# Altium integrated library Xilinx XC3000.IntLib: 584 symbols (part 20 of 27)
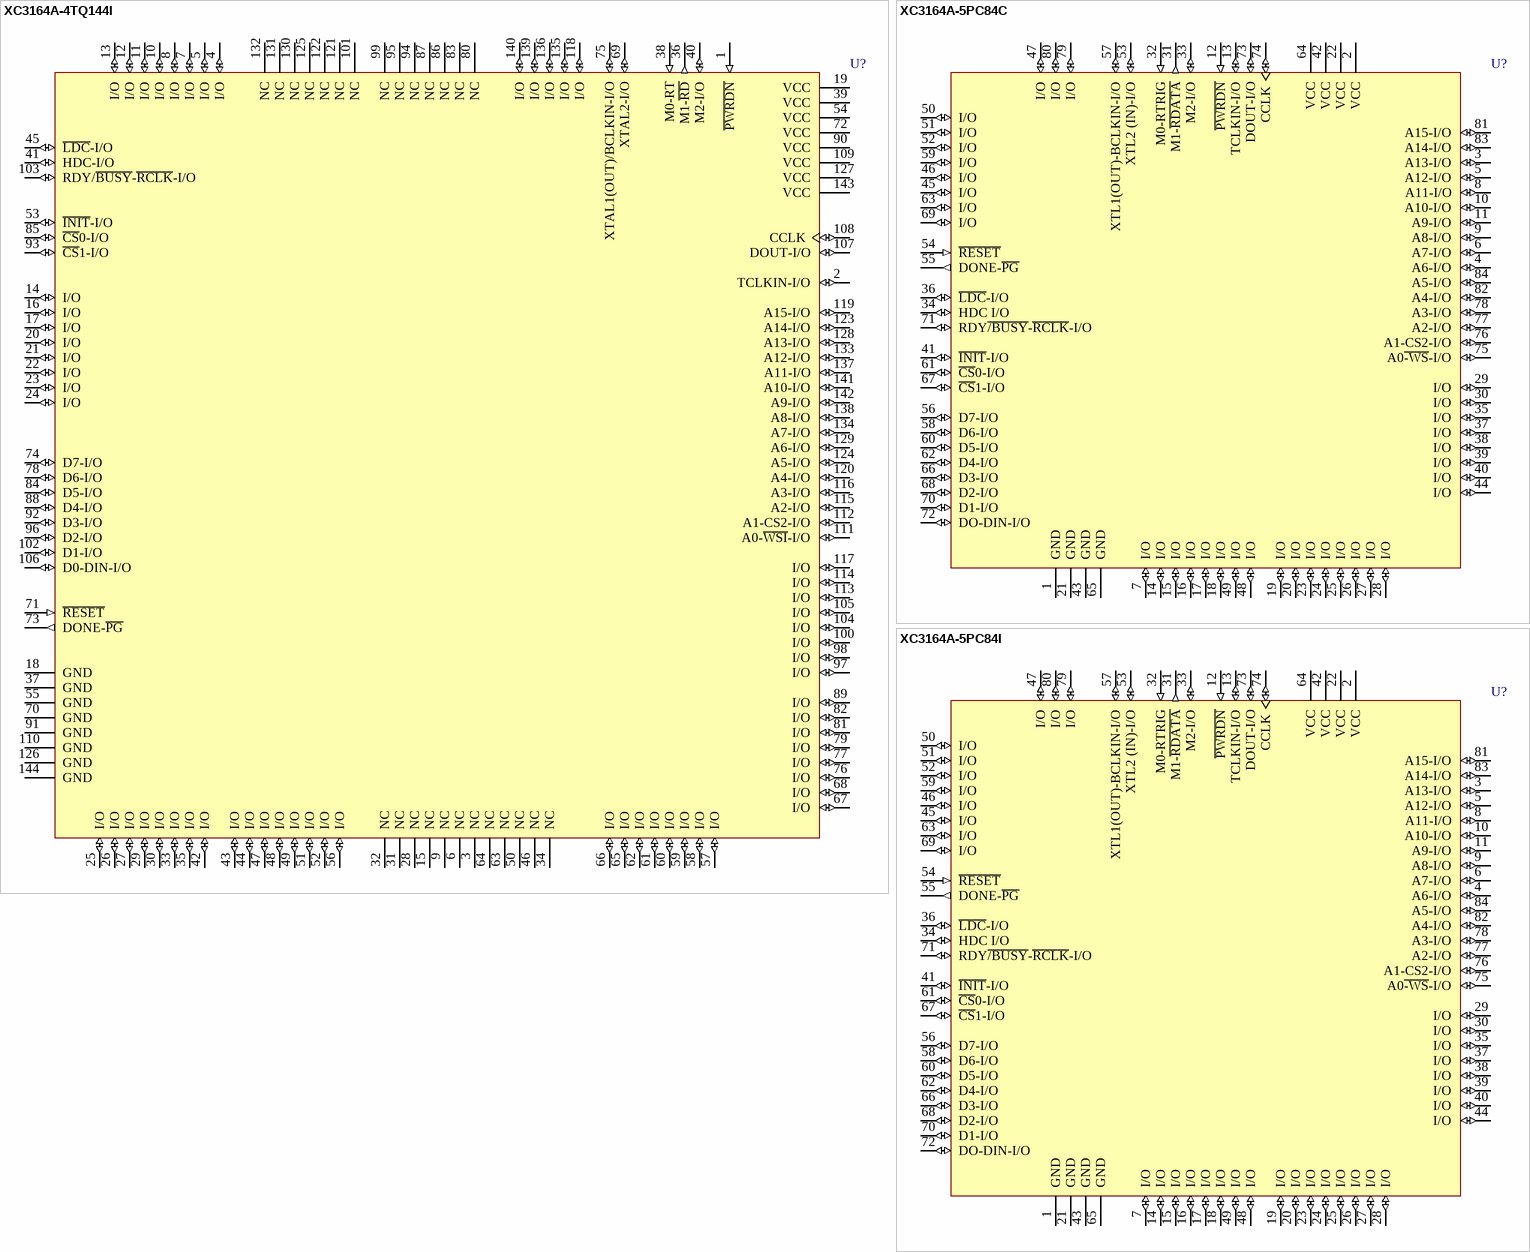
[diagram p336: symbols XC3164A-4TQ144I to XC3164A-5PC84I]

## XC3164A-5PC84I
designator U?
Logic Cell Array with 224 CLBs, with 68 I/O pins, 84-Pin PLCC, Industrial Grade; ComponentAvailability: Not for New Design
footprint PC84_N (Leaded Chip Carrier, 84-Leads, Body 29.3x29.3mm, Pitch 1.27mm, IPC Medium Density)
footprint PC84_L (Leaded Chip Carrier, 84-Leads, Body 29.3x29.3mm, Pitch 1.27mm, IPC High Density)
footprint PC84_M (Leaded Chip Carrier, 84-Leads, Body 29.3x29.3mm, Pitch 1.27mm, IPC Low Density)
3D model XC3164A-PC84 (84-Pin Plastic Leaded Chip Carrier (PC84))
pins: 1 GND (power), 2 VCC (power), 3 A13-I/O (io), 4 A6-I/O (io), 5 A12-I/O (io), 6 A7-I/O (io), 7 I/O (io), 8 A11-I/O (io), 9 A8-I/O (io), 10 A10-I/O (io), 11 A9-I/O (io), 12 ~{PWRDN} (in), 13 TCLKIN-I/O (io), 14 I/O (io), 15 I/O (io), 16 I/O (io), 17 I/O (io), 18 I/O (io), 19 I/O (io), 20 I/O (io), 21 GND (power), 22 VCC (power), 23 I/O (io), 24 I/O (io), 25 I/O (io), 26 I/O (io), 27 I/O (io), 28 I/O (io), 29 I/O (io), 30 I/O (io), 31 M1-~{RDATA} (out), 32 M0-RTRIG (in), 33 M2-I/O (io), 34 HDC I/O (io), 35 I/O (io), 36 ~{LDC}-I/O (io), 37 I/O (io), 38 I/O (io), 39 I/O (io), 40 I/O (io), 41 ~{INIT}-I/O (io), 42 VCC (power), 43 GND (power), 44 I/O (io), 45 I/O (io), 46 I/O (io), 47 I/O (io), 48 I/O (io), 49 I/O (io), 50 I/O (io), 51 I/O (io), 52 I/O (io), 53 XTL2 (IN)-I/O (io), 54 ~{RESET} (in), 55 DONE-~{PG} (out), 56 D7-I/O (io), 57 XTL1(OUT)-BCLKIN-I/O (io), 58 D6-I/O (io), 59 I/O (io), 60 D5-I/O (io), 61 ~{CS}0-I/O (io), 62 D4-I/O (io), 63 I/O (io), 64 VCC (power), 65 GND (power), 66 D3-I/O (io), 67 ~{CS}1-I/O (io), 68 D2-I/O (io), 69 I/O (io), 70 D1-I/O (io), 71 RDY~{/BUSY}-~{RCLK}-I/O (io), 72 DO-DIN-I/O (io), 73 DOUT-I/O (io), 74 CCLK (io), 75 A0~{-WS}-I/O (io), 76 A1-CS2-I/O (io), 77 A2-I/O (io), 78 A3-I/O (io), 79 I/O (io), 80 I/O (io), 81 A15-I/O (io), 82 A4-I/O (io), 83 A14-I/O (io), 84 A5-I/O (io)

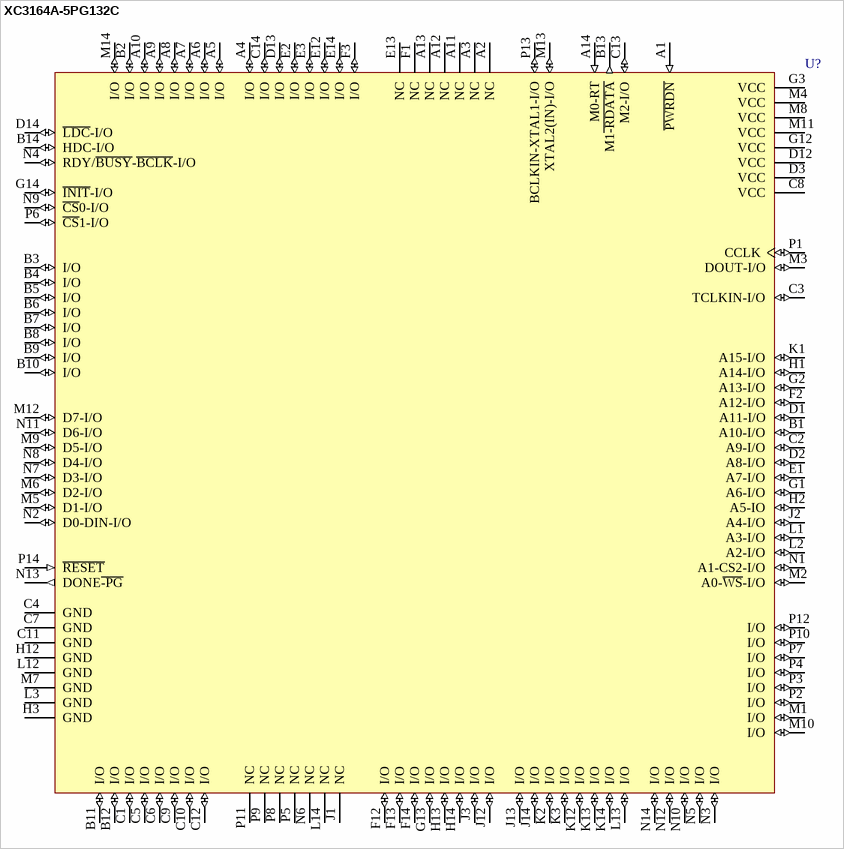
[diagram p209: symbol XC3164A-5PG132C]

## XC3164A-5PG132C
designator U?
Logic Cell Array with 224 CLBs, with 96 I/O Pins, 132-Pin PGA, Commercial Grade; ComponentAvailability: Not for New Design
footprint PG132 (PGA, 132-Leads, Body 37x37mm, Pitch 2.54mm)
3D model XC3164A-PG132 (132-Pin Ceramic Pin Grid Array (PG132))
pins: A1 ~{PWRDN} (in), A2 NC, A3 NC, A4 I/O (io), A5 I/O (io), A6 I/O (io), A7 I/O (io), A8 I/O (io), A9 I/O (io), A10 I/O (io), A11 NC, A12 NC, A13 NC, A14 M0-RT (in), B1 A10-I/O (io), B2 I/O (io), B3 I/O (io), B4 I/O (io), B5 I/O (io), B6 I/O (io), B7 I/O (io), B8 I/O (io), B9 I/O (io), B10 I/O (io), B11 I/O (io), B12 I/O (io), B13 M1~{-RDATA} (out), B14 HDC-I/O (io), C1 I/O (io), C2 A9-I/O (io), C3 TCLKIN-I/O (io), C4 GND (power), C5 I/O (io), C6 I/O (io), C7 GND (power), C8 VCC (power), C9 I/O (io), C10 I/O (io), C11 GND (power), C12 I/O (io), C13 M2-I/O (io), C14 I/O (io), D1 A11-I/O (io), D2 A8-I/O (io), D3 VCC (power), D12 VCC (power), D13 I/O (io), D14 ~{LDC}-I/O (io), E1 A7-I/O (io), E2 I/O (io), E3 I/O (io), E12 I/O (io), E13 NC, E14 I/O (io), F1 NC, F2 A12-I/O (io), F3 I/O (io), F12 I/O (io), F13 I/O (io), F14 I/O (io), G1 A6-I/O (io), G2 A13-I/O (io), G3 VCC (power), G12 VCC (power), G13 I/O (io), G14 ~{INIT}-I/O (io), H1 A14-I/O (io), H2 A5-IO (io), H3 GND (power), H12 GND (power), H13 I/O (io), H14 I/O (io), J1 NC, J2 A4-I/O (io), J3 I/O (io), J12 I/O (io), J13 I/O (io), J14 I/O (io), K1 A15-I/O (io), K2 I/O (io), K3 I/O (io), K12 I/O (io), K13 I/O (io), K14 I/O (io), L1 A3-I/O (io), L2 A2-I/O (io), L3 GND (power), L12 GND (power), L13 I/O (io), L14 NC, M1 I/O (io), M2 A0-~{WS}-I/O (io), M3 DOUT-I/O (io), M4 VCC (power), M5 D1-I/O (io), M6 D2-I/O (io), M7 GND (power), M8 VCC (power), M9 D5-I/O (io), M10 I/O (io), M11 VCC (power), M12 D7-I/O (io), M13 XTAL2(IN)-I/O (io), M14 I/O (io), N1 A1-CS2-I/O (io), N2 D0-DIN-I/O (io), N3 I/O (io), N4 RDY/~{BUSY}-~{BCLK}-I/O (io), N5 I/O (io), N6 NC, N7 D3-I/O (io), N8 D4-I/O (io), N9 ~{CS}0-I/O (io), N10 I/O (io), N11 D6-I/O (io), N12 I/O (io), N13 DONE~{-PG} (out), N14 I/O (io), P1 CCLK (io), P2 I/O (io), P3 I/O (io), P4 I/O (io), P5 NC, P6 ~{CS}1-I/O (io), P7 I/O (io), P8 NC, P9 NC, P10 I/O (io), P11 NC, P12 I/O (io), P13 BCLKIN-XTAL1-I/O (io), P14 ~{RESET} (in)

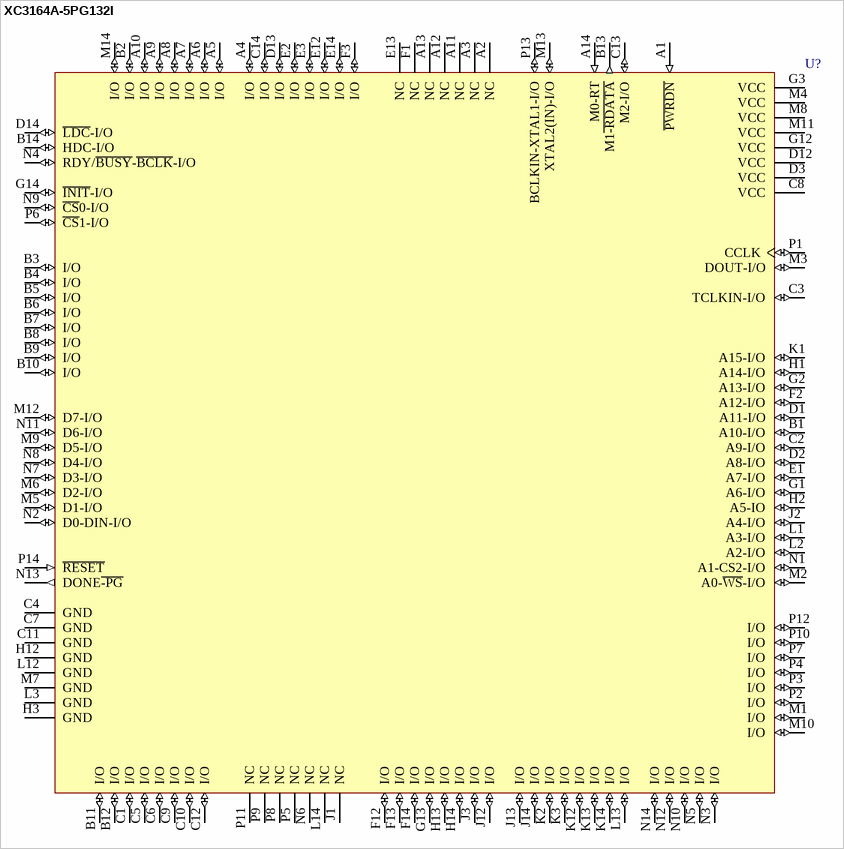
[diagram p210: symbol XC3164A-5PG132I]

## XC3164A-5PG132I
designator U?
Logic Cell Array with 224 CLBs, with 96 I/O Pins, 132-Pin PGA, Industrial Grade; ComponentAvailability: Not for New Design
footprint PG132 (PGA, 132-Leads, Body 37x37mm, Pitch 2.54mm)
3D model XC3164A-PG132 (132-Pin Ceramic Pin Grid Array (PG132))
pins: A1 ~{PWRDN} (in), A2 NC, A3 NC, A4 I/O (io), A5 I/O (io), A6 I/O (io), A7 I/O (io), A8 I/O (io), A9 I/O (io), A10 I/O (io), A11 NC, A12 NC, A13 NC, A14 M0-RT (in), B1 A10-I/O (io), B2 I/O (io), B3 I/O (io), B4 I/O (io), B5 I/O (io), B6 I/O (io), B7 I/O (io), B8 I/O (io), B9 I/O (io), B10 I/O (io), B11 I/O (io), B12 I/O (io), B13 M1~{-RDATA} (out), B14 HDC-I/O (io), C1 I/O (io), C2 A9-I/O (io), C3 TCLKIN-I/O (io), C4 GND (power), C5 I/O (io), C6 I/O (io), C7 GND (power), C8 VCC (power), C9 I/O (io), C10 I/O (io), C11 GND (power), C12 I/O (io), C13 M2-I/O (io), C14 I/O (io), D1 A11-I/O (io), D2 A8-I/O (io), D3 VCC (power), D12 VCC (power), D13 I/O (io), D14 ~{LDC}-I/O (io), E1 A7-I/O (io), E2 I/O (io), E3 I/O (io), E12 I/O (io), E13 NC, E14 I/O (io), F1 NC, F2 A12-I/O (io), F3 I/O (io), F12 I/O (io), F13 I/O (io), F14 I/O (io), G1 A6-I/O (io), G2 A13-I/O (io), G3 VCC (power), G12 VCC (power), G13 I/O (io), G14 ~{INIT}-I/O (io), H1 A14-I/O (io), H2 A5-IO (io), H3 GND (power), H12 GND (power), H13 I/O (io), H14 I/O (io), J1 NC, J2 A4-I/O (io), J3 I/O (io), J12 I/O (io), J13 I/O (io), J14 I/O (io), K1 A15-I/O (io), K2 I/O (io), K3 I/O (io), K12 I/O (io), K13 I/O (io), K14 I/O (io), L1 A3-I/O (io), L2 A2-I/O (io), L3 GND (power), L12 GND (power), L13 I/O (io), L14 NC, M1 I/O (io), M2 A0-~{WS}-I/O (io), M3 DOUT-I/O (io), M4 VCC (power), M5 D1-I/O (io), M6 D2-I/O (io), M7 GND (power), M8 VCC (power), M9 D5-I/O (io), M10 I/O (io), M11 VCC (power), M12 D7-I/O (io), M13 XTAL2(IN)-I/O (io), M14 I/O (io), N1 A1-CS2-I/O (io), N2 D0-DIN-I/O (io), N3 I/O (io), N4 RDY/~{BUSY}-~{BCLK}-I/O (io), N5 I/O (io), N6 NC, N7 D3-I/O (io), N8 D4-I/O (io), N9 ~{CS}0-I/O (io), N10 I/O (io), N11 D6-I/O (io), N12 I/O (io), N13 DONE~{-PG} (out), N14 I/O (io), P1 CCLK (io), P2 I/O (io), P3 I/O (io), P4 I/O (io), P5 NC, P6 ~{CS}1-I/O (io), P7 I/O (io), P8 NC, P9 NC, P10 I/O (io), P11 NC, P12 I/O (io), P13 BCLKIN-XTAL1-I/O (io), P14 ~{RESET} (in)

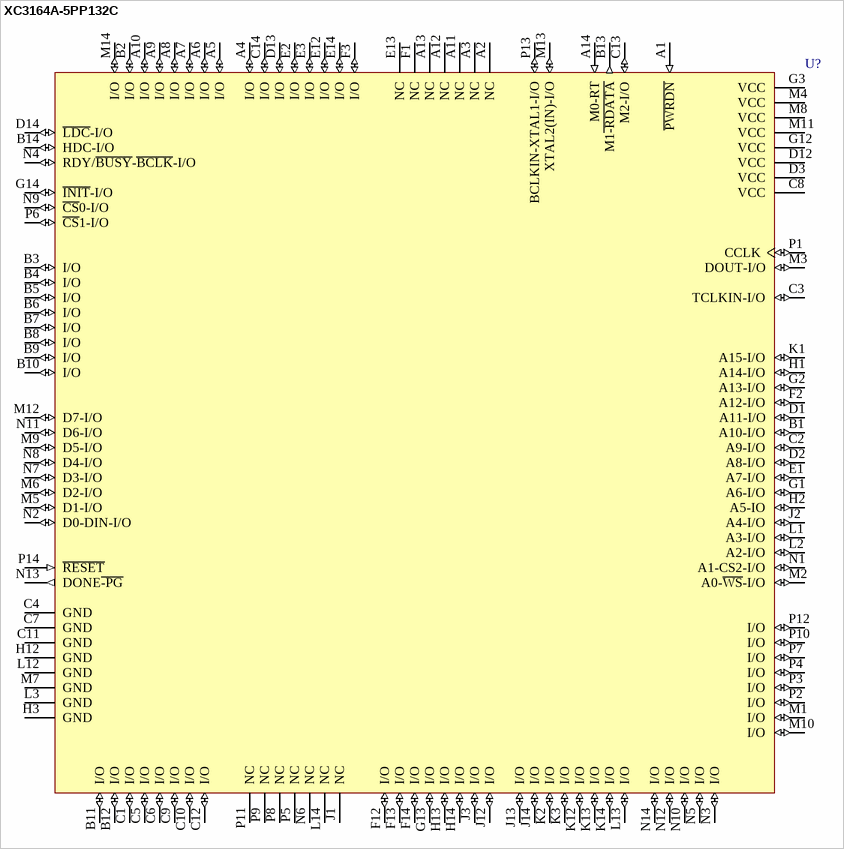
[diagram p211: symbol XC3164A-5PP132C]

## XC3164A-5PP132C
designator U?
Logic Cell Array with 224 CLBs, with 96 I/O Pins, 132-Pin PGA, Commercial Grade; ComponentAvailability: Not for New Design
footprint PP132 (PGA, 132-Leads, Body 37x37mm, Pitch 2.54mm)
3D model XC3164A-PP132 (132-Pin Plastic Pin Grid Array (PP132))
pins: A1 ~{PWRDN} (in), A2 NC, A3 NC, A4 I/O (io), A5 I/O (io), A6 I/O (io), A7 I/O (io), A8 I/O (io), A9 I/O (io), A10 I/O (io), A11 NC, A12 NC, A13 NC, A14 M0-RT (in), B1 A10-I/O (io), B2 I/O (io), B3 I/O (io), B4 I/O (io), B5 I/O (io), B6 I/O (io), B7 I/O (io), B8 I/O (io), B9 I/O (io), B10 I/O (io), B11 I/O (io), B12 I/O (io), B13 M1~{-RDATA} (out), B14 HDC-I/O (io), C1 I/O (io), C2 A9-I/O (io), C3 TCLKIN-I/O (io), C4 GND (power), C5 I/O (io), C6 I/O (io), C7 GND (power), C8 VCC (power), C9 I/O (io), C10 I/O (io), C11 GND (power), C12 I/O (io), C13 M2-I/O (io), C14 I/O (io), D1 A11-I/O (io), D2 A8-I/O (io), D3 VCC (power), D12 VCC (power), D13 I/O (io), D14 ~{LDC}-I/O (io), E1 A7-I/O (io), E2 I/O (io), E3 I/O (io), E12 I/O (io), E13 NC, E14 I/O (io), F1 NC, F2 A12-I/O (io), F3 I/O (io), F12 I/O (io), F13 I/O (io), F14 I/O (io), G1 A6-I/O (io), G2 A13-I/O (io), G3 VCC (power), G12 VCC (power), G13 I/O (io), G14 ~{INIT}-I/O (io), H1 A14-I/O (io), H2 A5-IO (io), H3 GND (power), H12 GND (power), H13 I/O (io), H14 I/O (io), J1 NC, J2 A4-I/O (io), J3 I/O (io), J12 I/O (io), J13 I/O (io), J14 I/O (io), K1 A15-I/O (io), K2 I/O (io), K3 I/O (io), K12 I/O (io), K13 I/O (io), K14 I/O (io), L1 A3-I/O (io), L2 A2-I/O (io), L3 GND (power), L12 GND (power), L13 I/O (io), L14 NC, M1 I/O (io), M2 A0-~{WS}-I/O (io), M3 DOUT-I/O (io), M4 VCC (power), M5 D1-I/O (io), M6 D2-I/O (io), M7 GND (power), M8 VCC (power), M9 D5-I/O (io), M10 I/O (io), M11 VCC (power), M12 D7-I/O (io), M13 XTAL2(IN)-I/O (io), M14 I/O (io), N1 A1-CS2-I/O (io), N2 D0-DIN-I/O (io), N3 I/O (io), N4 RDY/~{BUSY}-~{BCLK}-I/O (io), N5 I/O (io), N6 NC, N7 D3-I/O (io), N8 D4-I/O (io), N9 ~{CS}0-I/O (io), N10 I/O (io), N11 D6-I/O (io), N12 I/O (io), N13 DONE~{-PG} (out), N14 I/O (io), P1 CCLK (io), P2 I/O (io), P3 I/O (io), P4 I/O (io), P5 NC, P6 ~{CS}1-I/O (io), P7 I/O (io), P8 NC, P9 NC, P10 I/O (io), P11 NC, P12 I/O (io), P13 BCLKIN-XTAL1-I/O (io), P14 ~{RESET} (in)

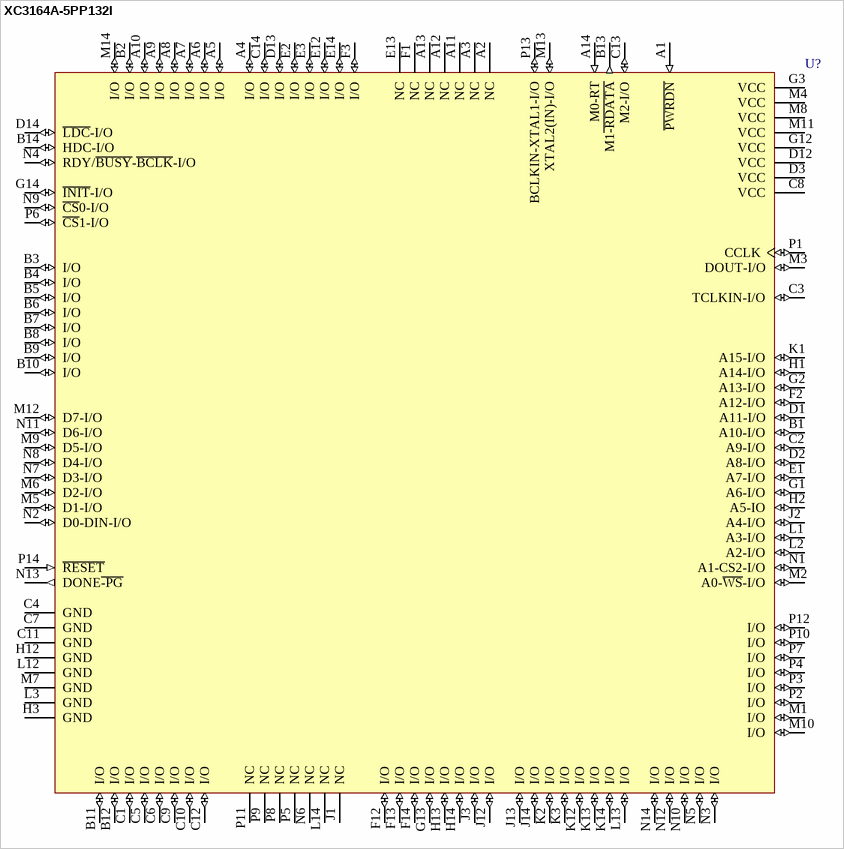
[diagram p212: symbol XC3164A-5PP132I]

## XC3164A-5PP132I
designator U?
Logic Cell Array with 224 CLBs, with 96 I/O Pins, 132-Pin PGA, Industrial Grade; ComponentAvailability: Not for New Design
footprint PP132 (PGA, 132-Leads, Body 37x37mm, Pitch 2.54mm)
3D model XC3164A-PP132 (132-Pin Plastic Pin Grid Array (PP132))
pins: A1 ~{PWRDN} (in), A2 NC, A3 NC, A4 I/O (io), A5 I/O (io), A6 I/O (io), A7 I/O (io), A8 I/O (io), A9 I/O (io), A10 I/O (io), A11 NC, A12 NC, A13 NC, A14 M0-RT (in), B1 A10-I/O (io), B2 I/O (io), B3 I/O (io), B4 I/O (io), B5 I/O (io), B6 I/O (io), B7 I/O (io), B8 I/O (io), B9 I/O (io), B10 I/O (io), B11 I/O (io), B12 I/O (io), B13 M1~{-RDATA} (out), B14 HDC-I/O (io), C1 I/O (io), C2 A9-I/O (io), C3 TCLKIN-I/O (io), C4 GND (power), C5 I/O (io), C6 I/O (io), C7 GND (power), C8 VCC (power), C9 I/O (io), C10 I/O (io), C11 GND (power), C12 I/O (io), C13 M2-I/O (io), C14 I/O (io), D1 A11-I/O (io), D2 A8-I/O (io), D3 VCC (power), D12 VCC (power), D13 I/O (io), D14 ~{LDC}-I/O (io), E1 A7-I/O (io), E2 I/O (io), E3 I/O (io), E12 I/O (io), E13 NC, E14 I/O (io), F1 NC, F2 A12-I/O (io), F3 I/O (io), F12 I/O (io), F13 I/O (io), F14 I/O (io), G1 A6-I/O (io), G2 A13-I/O (io), G3 VCC (power), G12 VCC (power), G13 I/O (io), G14 ~{INIT}-I/O (io), H1 A14-I/O (io), H2 A5-IO (io), H3 GND (power), H12 GND (power), H13 I/O (io), H14 I/O (io), J1 NC, J2 A4-I/O (io), J3 I/O (io), J12 I/O (io), J13 I/O (io), J14 I/O (io), K1 A15-I/O (io), K2 I/O (io), K3 I/O (io), K12 I/O (io), K13 I/O (io), K14 I/O (io), L1 A3-I/O (io), L2 A2-I/O (io), L3 GND (power), L12 GND (power), L13 I/O (io), L14 NC, M1 I/O (io), M2 A0-~{WS}-I/O (io), M3 DOUT-I/O (io), M4 VCC (power), M5 D1-I/O (io), M6 D2-I/O (io), M7 GND (power), M8 VCC (power), M9 D5-I/O (io), M10 I/O (io), M11 VCC (power), M12 D7-I/O (io), M13 XTAL2(IN)-I/O (io), M14 I/O (io), N1 A1-CS2-I/O (io), N2 D0-DIN-I/O (io), N3 I/O (io), N4 RDY/~{BUSY}-~{BCLK}-I/O (io), N5 I/O (io), N6 NC, N7 D3-I/O (io), N8 D4-I/O (io), N9 ~{CS}0-I/O (io), N10 I/O (io), N11 D6-I/O (io), N12 I/O (io), N13 DONE~{-PG} (out), N14 I/O (io), P1 CCLK (io), P2 I/O (io), P3 I/O (io), P4 I/O (io), P5 NC, P6 ~{CS}1-I/O (io), P7 I/O (io), P8 NC, P9 NC, P10 I/O (io), P11 NC, P12 I/O (io), P13 BCLKIN-XTAL1-I/O (io), P14 ~{RESET} (in)

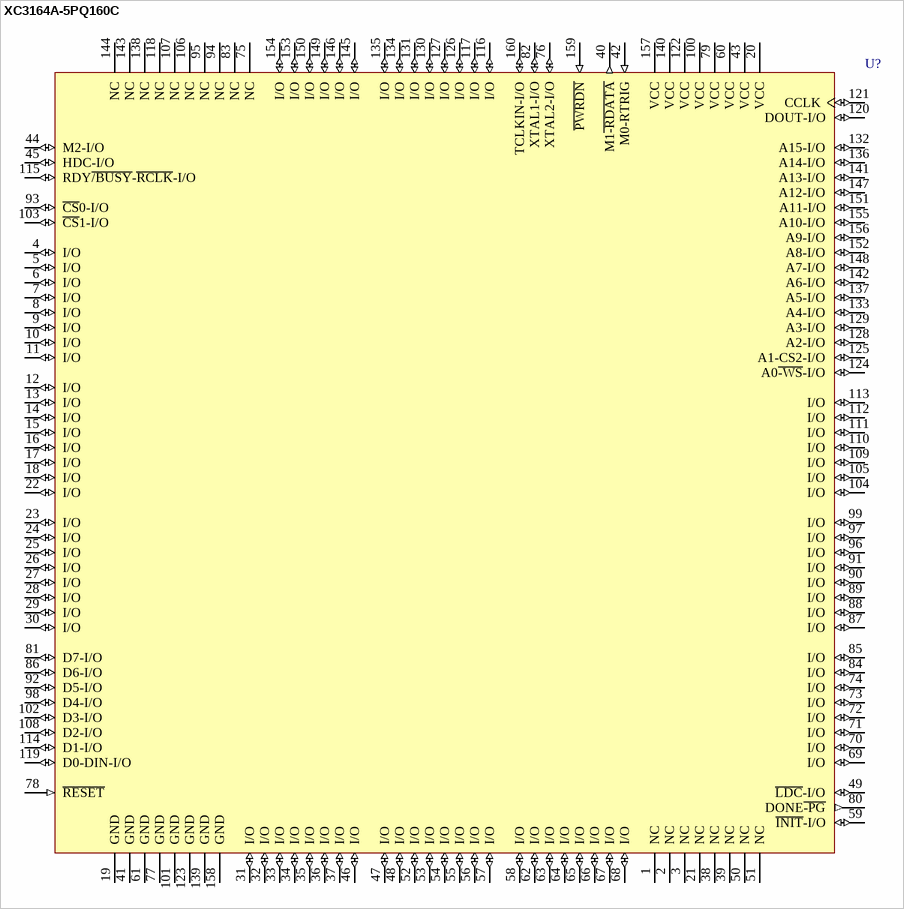
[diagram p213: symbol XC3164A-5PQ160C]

## XC3164A-5PQ160C
designator U?
Logic Cell Array with 224 CLBs, with 120 I/O Pins, 160-Pin PQFP, Commercial Grade; ComponentAvailability: Not for New Design
footprint PQ160_N (QFP, 160-Leads, Body 28 x 28mm, Pitch 0.65mm, IPC Medium Density)
footprint PQ160_L (QFP, 160-Leads, Body 28 x 28mm, Pitch 0.65mm, IPC High Density)
footprint PQ160_M (QFP, 160-Leads, Body 28 x 28mm, Pitch 0.65mm, IPC Low Density)
3D model XC3164A-PQ160 (160-Pin Plastic Quad Flat Pack (PQ160))
pins: 1 NC, 2 NC, 3 NC, 4 I/O (io), 5 I/O (io), 6 I/O (io), 7 I/O (io), 8 I/O (io), 9 I/O (io), 10 I/O (io), 11 I/O (io), 12 I/O (io), 13 I/O (io), 14 I/O (io), 15 I/O (io), 16 I/O (io), 17 I/O (io), 18 I/O (io), 19 GND (power), 20 VCC (power), 21 NC, 22 I/O (io), 23 I/O (io), 24 I/O (io), 25 I/O (io), 26 I/O (io), 27 I/O (io), 28 I/O (io), 29 I/O (io), 30 I/O (io), 31 I/O (io), 32 I/O (io), 33 I/O (io), 34 I/O (io), 35 I/O (io), 36 I/O (io), 37 I/O (io), 38 NC, 39 NC, 40 M1~{-RDATA} (out), 41 GND (power), 42 M0-RTRIG (in), 43 VCC (power), 44 M2-I/O (io), 45 HDC-I/O (io), 46 I/O (io), 47 I/O (io), 48 I/O (io), 49 ~{LDC}-I/O (io), 50 NC, 51 NC, 52 I/O (io), 53 I/O (io), 54 I/O (io), 55 I/O (io), 56 I/O (io), 57 I/O (io), 58 I/O (io), 59 ~{INIT}-I/O (io), 60 VCC (power), 61 GND (power), 62 I/O (io), 63 I/O (io), 64 I/O (io), 65 I/O (io), 66 I/O (io), 67 I/O (io), 68 I/O (io), 69 I/O (io), 70 I/O (io), 71 I/O (io), 72 I/O (io), 73 I/O (io), 74 I/O (io), 75 NC, 76 XTAL2-I/O (io), 77 GND (power), 78 ~{RESET} (in), 79 VCC (power), 80 DONE~{-PG} (out), 81 D7-I/O (io), 82 XTAL1-I/O (io), 83 NC, 84 I/O (io), 85 I/O (io), 86 D6-I/O (io), 87 I/O (io), 88 I/O (io), 89 I/O (io), 90 I/O (io), 91 I/O (io), 92 D5-I/O (io), 93 ~{CS}0-I/O (io), 94 NC, 95 NC, 96 I/O (io), 97 I/O (io), 98 D4-I/O (io), 99 I/O (io), 100 VCC (power), 101 GND (power), 102 D3-I/O (io), 103 ~{CS}1-I/O (io), 104 I/O (io), 105 I/O (io), 106 NC, 107 NC, 108 D2-I/O (io), 109 I/O (io), 110 I/O (io), 111 I/O (io), 112 I/O (io), 113 I/O (io), 114 D1-I/O (io), 115 RDY~{/BUSY}-~{RCLK}-I/O (io), 116 I/O (io), 117 I/O (io), 118 NC, 119 D0-DIN-I/O (io), 120 DOUT-I/O (io), 121 CCLK (io), 122 VCC (power), 123 GND (power), 124 A0~{-WS}-I/O (io), 125 A1-CS2-I/O (io), 126 I/O (io), 127 I/O (io), 128 A2-I/O (io), 129 A3-I/O (io), 130 I/O (io), 131 I/O (io), 132 A15-I/O (io), 133 A4-I/O (io), 134 I/O (io), 135 I/O (io), 136 A14-I/O (io), 137 A5-I/O (io), 138 NC, 139 GND (power), 140 VCC (power), 141 A13-I/O (io), 142 A6-I/O (io), 143 NC, 144 NC, 145 I/O (io), 146 I/O (io), 147 A12-I/O (io), 148 A7-I/O (io), 149 I/O (io), 150 I/O (io), 151 A11-I/O (io), 152 A8-I/O (io), 153 I/O (io), 154 I/O (io), 155 A10-I/O (io), 156 A9-I/O (io), 157 VCC (power), 158 GND (power), 159 ~{PWRDN} (in), 160 TCLKIN-I/O (io)

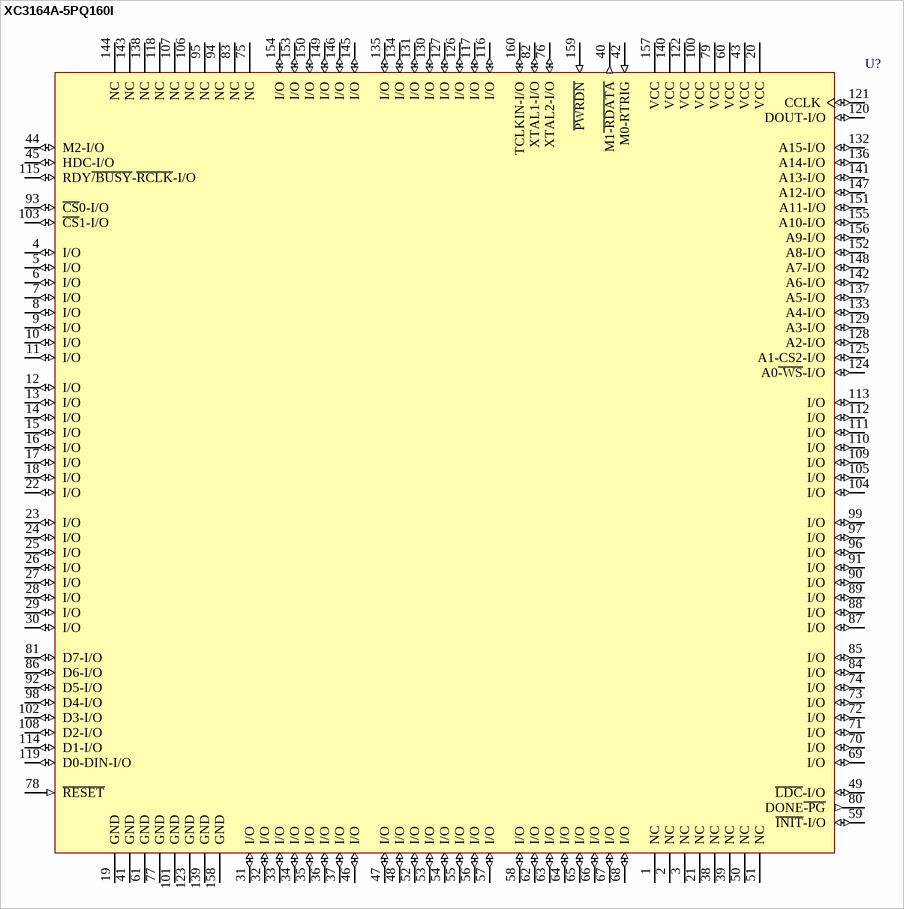
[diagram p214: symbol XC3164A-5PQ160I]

## XC3164A-5PQ160I
designator U?
Logic Cell Array with 224 CLBs, with 120 I/O Pins, 160-Pin PQFP, Industrial Grade; ComponentAvailability: Not for New Design
footprint PQ160_N (QFP, 160-Leads, Body 28 x 28mm, Pitch 0.65mm, IPC Medium Density)
footprint PQ160_L (QFP, 160-Leads, Body 28 x 28mm, Pitch 0.65mm, IPC High Density)
footprint PQ160_M (QFP, 160-Leads, Body 28 x 28mm, Pitch 0.65mm, IPC Low Density)
3D model XC3164A-PQ160 (160-Pin Plastic Quad Flat Pack (PQ160))
pins: 1 NC, 2 NC, 3 NC, 4 I/O (io), 5 I/O (io), 6 I/O (io), 7 I/O (io), 8 I/O (io), 9 I/O (io), 10 I/O (io), 11 I/O (io), 12 I/O (io), 13 I/O (io), 14 I/O (io), 15 I/O (io), 16 I/O (io), 17 I/O (io), 18 I/O (io), 19 GND (power), 20 VCC (power), 21 NC, 22 I/O (io), 23 I/O (io), 24 I/O (io), 25 I/O (io), 26 I/O (io), 27 I/O (io), 28 I/O (io), 29 I/O (io), 30 I/O (io), 31 I/O (io), 32 I/O (io), 33 I/O (io), 34 I/O (io), 35 I/O (io), 36 I/O (io), 37 I/O (io), 38 NC, 39 NC, 40 M1~{-RDATA} (out), 41 GND (power), 42 M0-RTRIG (in), 43 VCC (power), 44 M2-I/O (io), 45 HDC-I/O (io), 46 I/O (io), 47 I/O (io), 48 I/O (io), 49 ~{LDC}-I/O (io), 50 NC, 51 NC, 52 I/O (io), 53 I/O (io), 54 I/O (io), 55 I/O (io), 56 I/O (io), 57 I/O (io), 58 I/O (io), 59 ~{INIT}-I/O (io), 60 VCC (power), 61 GND (power), 62 I/O (io), 63 I/O (io), 64 I/O (io), 65 I/O (io), 66 I/O (io), 67 I/O (io), 68 I/O (io), 69 I/O (io), 70 I/O (io), 71 I/O (io), 72 I/O (io), 73 I/O (io), 74 I/O (io), 75 NC, 76 XTAL2-I/O (io), 77 GND (power), 78 ~{RESET} (in), 79 VCC (power), 80 DONE~{-PG} (out), 81 D7-I/O (io), 82 XTAL1-I/O (io), 83 NC, 84 I/O (io), 85 I/O (io), 86 D6-I/O (io), 87 I/O (io), 88 I/O (io), 89 I/O (io), 90 I/O (io), 91 I/O (io), 92 D5-I/O (io), 93 ~{CS}0-I/O (io), 94 NC, 95 NC, 96 I/O (io), 97 I/O (io), 98 D4-I/O (io), 99 I/O (io), 100 VCC (power), 101 GND (power), 102 D3-I/O (io), 103 ~{CS}1-I/O (io), 104 I/O (io), 105 I/O (io), 106 NC, 107 NC, 108 D2-I/O (io), 109 I/O (io), 110 I/O (io), 111 I/O (io), 112 I/O (io), 113 I/O (io), 114 D1-I/O (io), 115 RDY~{/BUSY}-~{RCLK}-I/O (io), 116 I/O (io), 117 I/O (io), 118 NC, 119 D0-DIN-I/O (io), 120 DOUT-I/O (io), 121 CCLK (io), 122 VCC (power), 123 GND (power), 124 A0~{-WS}-I/O (io), 125 A1-CS2-I/O (io), 126 I/O (io), 127 I/O (io), 128 A2-I/O (io), 129 A3-I/O (io), 130 I/O (io), 131 I/O (io), 132 A15-I/O (io), 133 A4-I/O (io), 134 I/O (io), 135 I/O (io), 136 A14-I/O (io), 137 A5-I/O (io), 138 NC, 139 GND (power), 140 VCC (power), 141 A13-I/O (io), 142 A6-I/O (io), 143 NC, 144 NC, 145 I/O (io), 146 I/O (io), 147 A12-I/O (io), 148 A7-I/O (io), 149 I/O (io), 150 I/O (io), 151 A11-I/O (io), 152 A8-I/O (io), 153 I/O (io), 154 I/O (io), 155 A10-I/O (io), 156 A9-I/O (io), 157 VCC (power), 158 GND (power), 159 ~{PWRDN} (in), 160 TCLKIN-I/O (io)

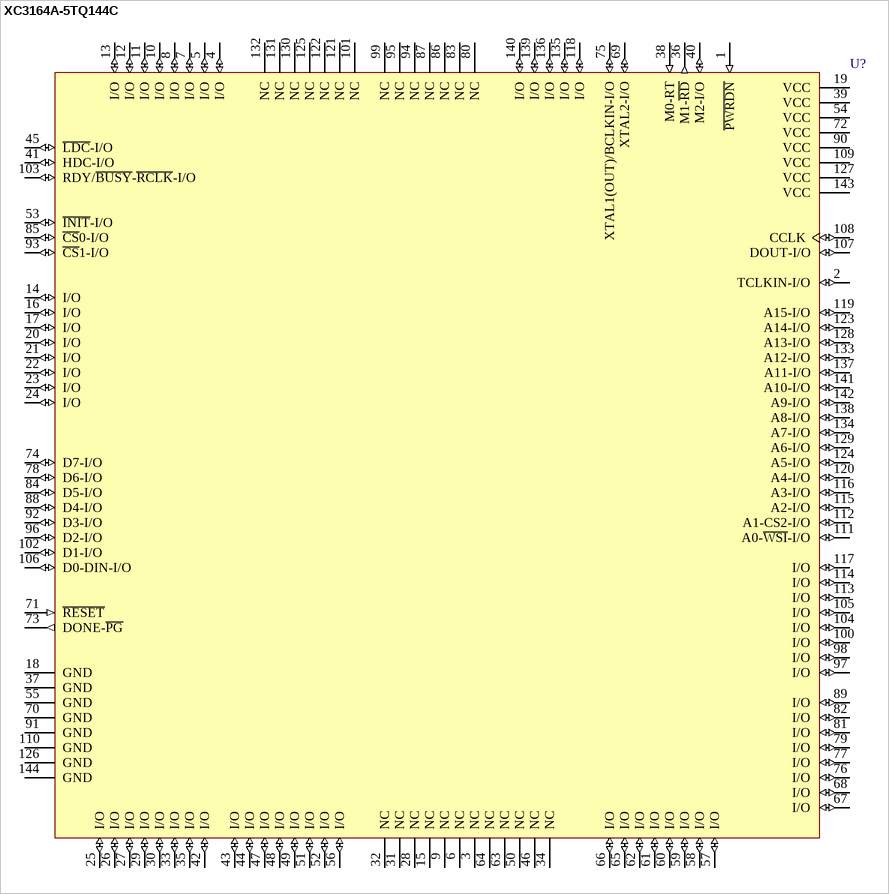
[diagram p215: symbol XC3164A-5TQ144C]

## XC3164A-5TQ144C
designator U?
Logic Cell Array with 224 CLBs, with 96 I/O Pins, 144-Pin TQFP, Commercial Grade; ComponentAvailability: Not for New Design
footprint TQ144_N (Thin QFP, 144-Leads, Body 20x20mm, Pitch 0.5mm, IPC Medium Density)
footprint TQ144_L (Thin QFP, 144-Leads, Body 20x20mm, Pitch 0.5mm, IPC High Density)
footprint TQ144_M (Thin QFP, 144-Leads, Body 20x20mm, Pitch 0.5mm, IPC Low Density)
3D model XC3164A-TQ144 (144-Pin Thin Quad Flat Pack (TQ144))
pins: 1 ~{PWRDN} (in), 2 TCLKIN-I/O (io), 3 NC, 4 I/O (io), 5 I/O (io), 6 NC, 7 I/O (io), 8 I/O (io), 9 NC, 10 I/O (io), 11 I/O (io), 12 I/O (io), 13 I/O (io), 14 I/O (io), 15 NC, 16 I/O (io), 17 I/O (io), 18 GND (power), 19 VCC (power), 20 I/O (io), 21 I/O (io), 22 I/O (io), 23 I/O (io), 24 I/O (io), 25 I/O (io), 26 I/O (io), 27 I/O (io), 28 NC, 29 I/O (io), 30 I/O (io), 31 NC, 32 NC, 33 I/O (io), 34 NC, 35 I/O (io), 36 M1-~{RD} (out), 37 GND (power), 38 M0-RT (in), 39 VCC (power), 40 M2-I/O (io), 41 HDC-I/O (io), 42 I/O (io), 43 I/O (io), 44 I/O (io), 45 ~{LDC}-I/O (io), 46 NC, 47 I/O (io), 48 I/O (io), 49 I/O (io), 50 NC, 51 I/O (io), 52 I/O (io), 53 ~{INIT}-I/O (io), 54 VCC (power), 55 GND (power), 56 I/O (io), 57 I/O (io), 58 I/O (io), 59 I/O (io), 60 I/O (io), 61 I/O (io), 62 I/O (io), 63 NC, 64 NC, 65 I/O (io), 66 I/O (io), 67 I/O (io), 68 I/O (io), 69 XTAL2-I/O (io), 70 GND (power), 71 ~{RESET} (in), 72 VCC (power), 73 DONE-~{PG} (out), 74 D7-I/O (io), 75 XTAL1(OUT)/BCLKIN-I/O (io), 76 I/O (io), 77 I/O (io), 78 D6-I/O (io), 79 I/O (io), 80 NC, 81 I/O (io), 82 I/O (io), 83 NC, 84 D5-I/O (io), 85 ~{CS}0-I/O (io), 86 NC, 87 NC, 88 D4-I/O (io), 89 I/O (io), 90 VCC (power), 91 GND (power), 92 D3-I/O (io), 93 ~{CS}1-I/O (io), 94 NC, 95 NC, 96 D2-I/O (io), 97 I/O (io), 98 I/O (io), 99 NC, 100 I/O (io), 101 NC, 102 D1-I/O (io), 103 RDY/~{BUSY}-~{RCLK}-I/O (io), 104 I/O (io), 105 I/O (io), 106 D0-DIN-I/O (io), 107 DOUT-I/O (io), 108 CCLK (io), 109 VCC (power), 110 GND (power), 111 A0-~{WSI}-I/O (io), 112 A1-CS2-I/O (io), 113 I/O (io), 114 I/O (io), 115 A2-I/O (io), 116 A3-I/O (io), 117 I/O (io), 118 I/O (io), 119 A15-I/O (io), 120 A4-I/O (io), 121 NC, 122 NC, 123 A14-I/O (io), 124 A5-I/O (io), 125 NC, 126 GND (power), 127 VCC (power), 128 A13-I/O (io), 129 A6-I/O (io), 130 NC, 131 NC, 132 NC, 133 A12-I/O (io), 134 A7-I/O (io), 135 I/O (io), 136 I/O (io), 137 A11-I/O (io), 138 A8-I/O (io), 139 I/O (io), 140 I/O (io), 141 A10-I/O (io), 142 A9-I/O (io), 143 VCC (power), 144 GND (power)

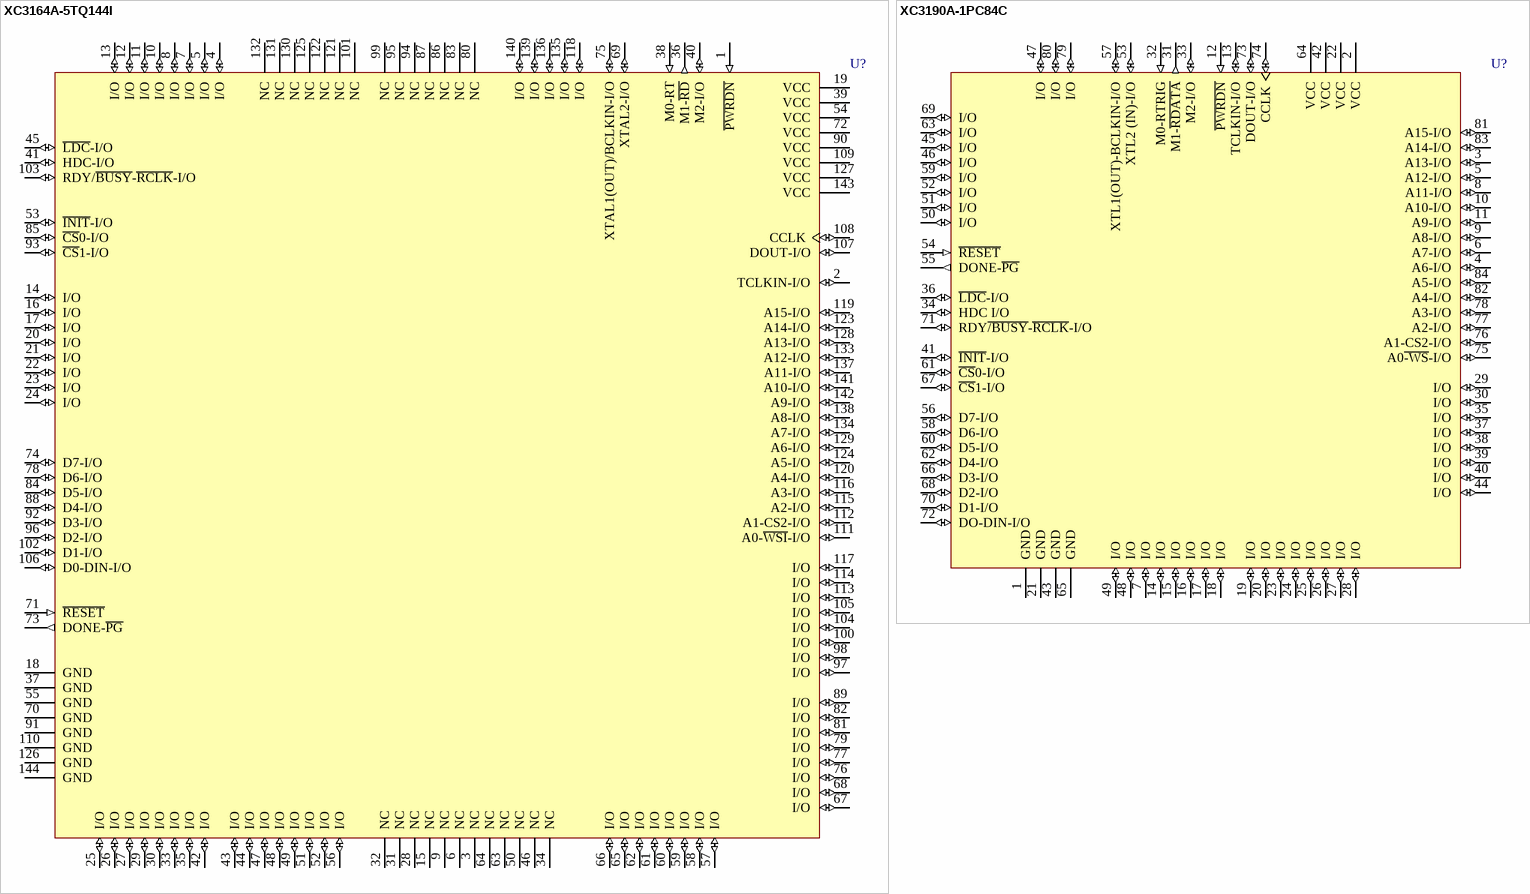
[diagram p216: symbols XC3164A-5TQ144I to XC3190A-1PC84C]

## XC3164A-5TQ144I
designator U?
Logic Cell Array with 224 CLBs, with 96 I/O Pins, 144-Pin TQFP, Industrial Grade; ComponentAvailability: Not for New Design
footprint TQ144_N (Thin QFP, 144-Leads, Body 20x20mm, Pitch 0.5mm, IPC Medium Density)
footprint TQ144_L (Thin QFP, 144-Leads, Body 20x20mm, Pitch 0.5mm, IPC High Density)
footprint TQ144_M (Thin QFP, 144-Leads, Body 20x20mm, Pitch 0.5mm, IPC Low Density)
3D model XC3164A-TQ144 (144-Pin Thin Quad Flat Pack (TQ144))
pins: 1 ~{PWRDN} (in), 2 TCLKIN-I/O (io), 3 NC, 4 I/O (io), 5 I/O (io), 6 NC, 7 I/O (io), 8 I/O (io), 9 NC, 10 I/O (io), 11 I/O (io), 12 I/O (io), 13 I/O (io), 14 I/O (io), 15 NC, 16 I/O (io), 17 I/O (io), 18 GND (power), 19 VCC (power), 20 I/O (io), 21 I/O (io), 22 I/O (io), 23 I/O (io), 24 I/O (io), 25 I/O (io), 26 I/O (io), 27 I/O (io), 28 NC, 29 I/O (io), 30 I/O (io), 31 NC, 32 NC, 33 I/O (io), 34 NC, 35 I/O (io), 36 M1-~{RD} (out), 37 GND (power), 38 M0-RT (in), 39 VCC (power), 40 M2-I/O (io), 41 HDC-I/O (io), 42 I/O (io), 43 I/O (io), 44 I/O (io), 45 ~{LDC}-I/O (io), 46 NC, 47 I/O (io), 48 I/O (io), 49 I/O (io), 50 NC, 51 I/O (io), 52 I/O (io), 53 ~{INIT}-I/O (io), 54 VCC (power), 55 GND (power), 56 I/O (io), 57 I/O (io), 58 I/O (io), 59 I/O (io), 60 I/O (io), 61 I/O (io), 62 I/O (io), 63 NC, 64 NC, 65 I/O (io), 66 I/O (io), 67 I/O (io), 68 I/O (io), 69 XTAL2-I/O (io), 70 GND (power), 71 ~{RESET} (in), 72 VCC (power), 73 DONE-~{PG} (out), 74 D7-I/O (io), 75 XTAL1(OUT)/BCLKIN-I/O (io), 76 I/O (io), 77 I/O (io), 78 D6-I/O (io), 79 I/O (io), 80 NC, 81 I/O (io), 82 I/O (io), 83 NC, 84 D5-I/O (io), 85 ~{CS}0-I/O (io), 86 NC, 87 NC, 88 D4-I/O (io), 89 I/O (io), 90 VCC (power), 91 GND (power), 92 D3-I/O (io), 93 ~{CS}1-I/O (io), 94 NC, 95 NC, 96 D2-I/O (io), 97 I/O (io), 98 I/O (io), 99 NC, 100 I/O (io), 101 NC, 102 D1-I/O (io), 103 RDY/~{BUSY}-~{RCLK}-I/O (io), 104 I/O (io), 105 I/O (io), 106 D0-DIN-I/O (io), 107 DOUT-I/O (io), 108 CCLK (io), 109 VCC (power), 110 GND (power), 111 A0-~{WSI}-I/O (io), 112 A1-CS2-I/O (io), 113 I/O (io), 114 I/O (io), 115 A2-I/O (io), 116 A3-I/O (io), 117 I/O (io), 118 I/O (io), 119 A15-I/O (io), 120 A4-I/O (io), 121 NC, 122 NC, 123 A14-I/O (io), 124 A5-I/O (io), 125 NC, 126 GND (power), 127 VCC (power), 128 A13-I/O (io), 129 A6-I/O (io), 130 NC, 131 NC, 132 NC, 133 A12-I/O (io), 134 A7-I/O (io), 135 I/O (io), 136 I/O (io), 137 A11-I/O (io), 138 A8-I/O (io), 139 I/O (io), 140 I/O (io), 141 A10-I/O (io), 142 A9-I/O (io), 143 VCC (power), 144 GND (power)

## XC3190A-1PC84C
designator U?
Logic Cell Array with 320 CLBs, with 70 I/O Pins, 84-Pin PLCC, Commercial Grade; ComponentAvailability: Not for New Design
footprint PC84_N (Leaded Chip Carrier, 84-Leads, Body 29.3x29.3mm, Pitch 1.27mm, IPC Medium Density)
footprint PC84_L (Leaded Chip Carrier, 84-Leads, Body 29.3x29.3mm, Pitch 1.27mm, IPC High Density)
footprint PC84_M (Leaded Chip Carrier, 84-Leads, Body 29.3x29.3mm, Pitch 1.27mm, IPC Low Density)
3D model XC3190A-PC84 (84-Pin Plastic Leaded Chip Carrier (PC84))
pins: 1 GND (power), 2 VCC (power), 3 A13-I/O (io), 4 A6-I/O (io), 5 A12-I/O (io), 6 A7-I/O (io), 7 I/O (io), 8 A11-I/O (io), 9 A8-I/O (io), 10 A10-I/O (io), 11 A9-I/O (io), 12 ~{PWRDN} (in), 13 TCLKIN-I/O (io), 14 I/O (io), 15 I/O (io), 16 I/O (io), 17 I/O (io), 18 I/O (io), 19 I/O (io), 20 I/O (io), 21 GND (power), 22 VCC (power), 23 I/O (io), 24 I/O (io), 25 I/O (io), 26 I/O (io), 27 I/O (io), 28 I/O (io), 29 I/O (io), 30 I/O (io), 31 M1-~{RDATA} (out), 32 M0-RTRIG (in), 33 M2-I/O (io), 34 HDC I/O (io), 35 I/O (io), 36 ~{LDC}-I/O (io), 37 I/O (io), 38 I/O (io), 39 I/O (io), 40 I/O (io), 41 ~{INIT}-I/O (io), 42 VCC (power), 43 GND (power), 44 I/O (io), 45 I/O (io), 46 I/O (io), 47 I/O (io), 48 I/O (io), 49 I/O (io), 50 I/O (io), 51 I/O (io), 52 I/O (io), 53 XTL2 (IN)-I/O (io), 54 ~{RESET} (in), 55 DONE-~{PG} (out), 56 D7-I/O (io), 57 XTL1(OUT)-BCLKIN-I/O (io), 58 D6-I/O (io), 59 I/O (io), 60 D5-I/O (io), 61 ~{CS}0-I/O (io), 62 D4-I/O (io), 63 I/O (io), 64 VCC (power), 65 GND (power), 66 D3-I/O (io), 67 ~{CS}1-I/O (io), 68 D2-I/O (io), 69 I/O (io), 70 D1-I/O (io), 71 RDY~{/BUSY}-~{RCLK}-I/O (io), 72 DO-DIN-I/O (io), 73 DOUT-I/O (io), 74 CCLK (io), 75 A0~{-WS}-I/O (io), 76 A1-CS2-I/O (io), 77 A2-I/O (io), 78 A3-I/O (io), 79 I/O (io), 80 I/O (io), 81 A15-I/O (io), 82 A4-I/O (io), 83 A14-I/O (io), 84 A5-I/O (io)

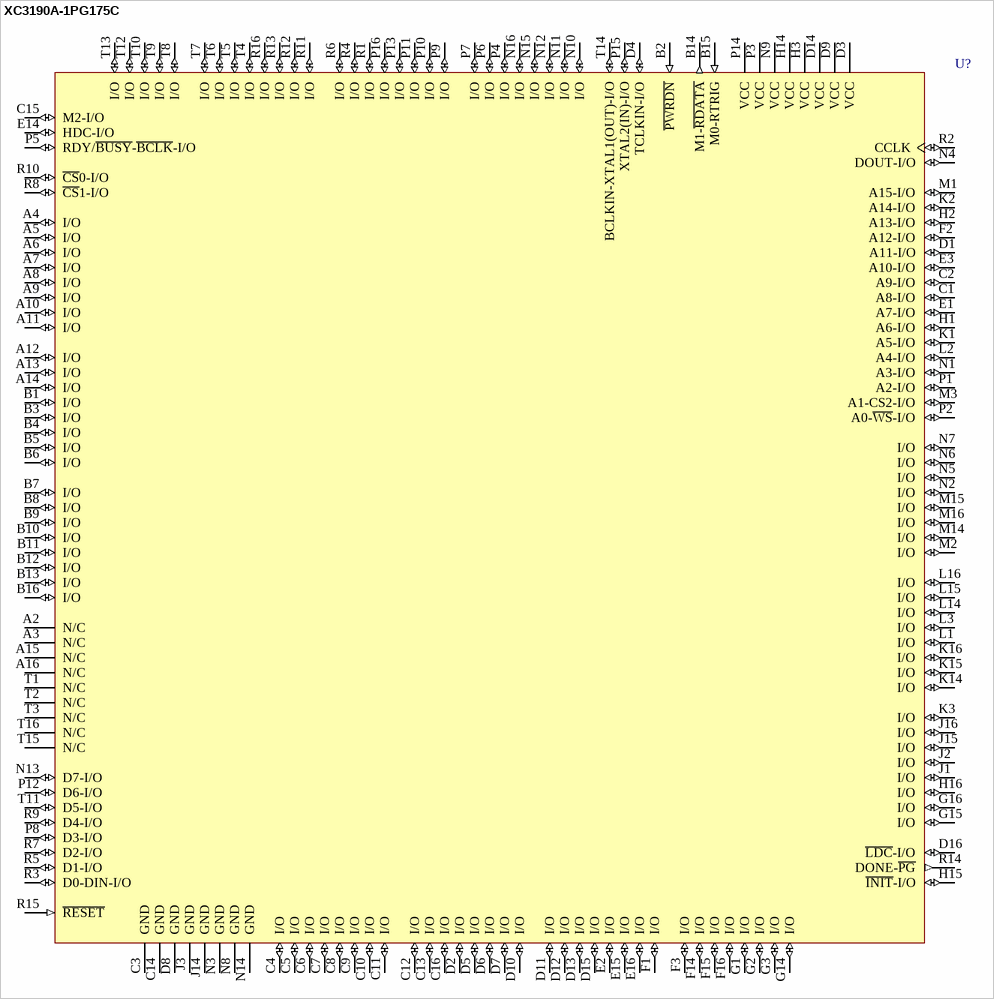
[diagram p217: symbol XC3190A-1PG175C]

## XC3190A-1PG175C
designator U?
Logic Cell Array with 320 CLBs, with 144 I/O Pins, 175-Pin PGA, Commercial Grade; ComponentAvailability: Not for New Design
footprint PG175 (PGA, 175-Leads, Body 42x42mm, Pitch 2.54mm)
3D model XC3190A-PG175 (175-Pin Ceramic Pin Grid Array (PG175))
pins: A2 N/C, A3 N/C, A4 I/O (io), A5 I/O (io), A6 I/O (io), A7 I/O (io), A8 I/O (io), A9 I/O (io), A10 I/O (io), A11 I/O (io), A12 I/O (io), A13 I/O (io), A14 I/O (io), A15 N/C, A16 N/C, B1 I/O (io), B2 ~{PWRDN} (in), B3 I/O (io), B4 I/O (io), B5 I/O (io), B6 I/O (io), B7 I/O (io), B8 I/O (io), B9 I/O (io), B10 I/O (io), B11 I/O (io), B12 I/O (io), B13 I/O (io), B14 M1-~{RDATA} (out), B15 M0-RTRIG (in), B16 I/O (io), C1 A8-I/O (io), C2 A9-I/O (io), C3 GND (power), C4 I/O (io), C5 I/O (io), C6 I/O (io), C7 I/O (io), C8 I/O (io), C9 I/O (io), C10 I/O (io), C11 I/O (io), C12 I/O (io), C13 I/O (io), C14 GND (power), C15 M2-I/O (io), C16 I/O (io), D1 A11-I/O (io), D2 I/O (io), D3 VCC (power), D4 TCLKIN-I/O (io), D5 I/O (io), D6 I/O (io), D7 I/O (io), D8 GND (power), D9 VCC (power), D10 I/O (io), D11 I/O (io), D12 I/O (io), D13 I/O (io), D14 VCC (power), D15 I/O (io), D16 ~{LDC}-I/O (io), E1 A7-I/O (io), E2 I/O (io), E3 A10-I/O (io), E14 HDC-I/O (io), E15 I/O (io), E16 I/O (io), F1 I/O (io), F2 A12-I/O (io), F3 I/O (io), F14 I/O (io), F15 I/O (io), F16 I/O (io), G1 I/O (io), G2 I/O (io), G3 I/O (io), G14 I/O (io), G15 I/O (io), G16 I/O (io), H1 A6-I/O (io), H2 A13-I/O (io), H3 VCC (power), H14 VCC (power), H15 ~{INIT}-I/O (io), H16 I/O (io), J1 I/O (io), J2 I/O (io), J3 GND (power), J14 GND (power), J15 I/O (io), J16 I/O (io), K1 A5-I/O (io), K2 A14-I/O (io), K3 I/O (io), K14 I/O (io), K15 I/O (io), K16 I/O (io), L1 I/O (io), L2 A4-I/O (io), L3 I/O (io), L14 I/O (io), L15 I/O (io), L16 I/O (io), M1 A15-I/O (io), M2 I/O (io), M3 A1-CS2-I/O (io), M14 I/O (io), M15 I/O (io), M16 I/O (io), N1 A3-I/O (io), N2 I/O (io), N3 GND (power), N4 DOUT-I/O (io), N5 I/O (io), N6 I/O (io), N7 I/O (io), N8 GND (power), N9 VCC (power), N10 I/O (io), N11 I/O (io), N12 I/O (io), N13 D7-I/O (io), N14 GND (power), N15 I/O (io), N16 I/O (io), P1 A2-I/O (io), P2 A0-~{WS}-I/O (io), P3 VCC (power), P4 I/O (io), P5 RDY/~{BUSY}-~{BCLK}-I/O (io), P6 I/O (io), P7 I/O (io), P8 D3-I/O (io), P9 I/O (io), P10 I/O (io), P11 I/O (io), P12 D6-I/O (io), P13 I/O (io), P14 VCC (power), P15 XTAL2(IN)-I/O (io), P16 I/O (io), R1 I/O (io), R2 CCLK (io), R3 D0-DIN-I/O (io), R4 I/O (io), R5 D1-I/O (io), R6 I/O (io), R7 D2-I/O (io), R8 ~{CS}1-I/O (io), R9 D4-I/O (io), R10 ~{CS}0-I/O (io), R11 I/O (io), R12 I/O (io), R13 I/O (io), R14 DONE-~{PG} (out), R15 ~{RESET} (in), R16 I/O (io), T1 N/C, T2 N/C, T3 N/C, T4 I/O (io), T5 I/O (io), T6 I/O (io), T7 I/O (io), T8 I/O (io), T9 I/O (io), T10 I/O (io), T11 D5-I/O (io), T12 I/O (io), T13 I/O (io), T14 BCLKIN-XTAL1(OUT)-I/O (io), T15 N/C, T16 N/C

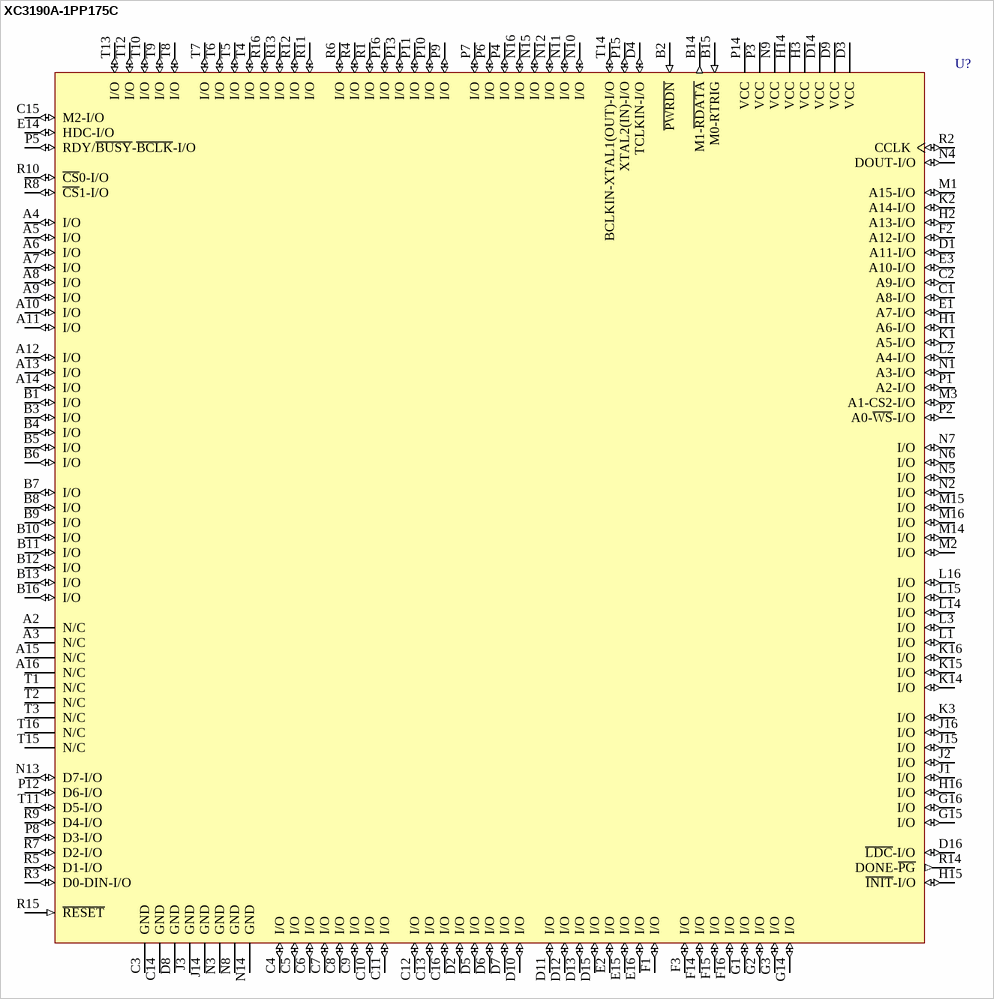
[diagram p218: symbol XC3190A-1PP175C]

## XC3190A-1PP175C
designator U?
Logic Cell Array with 320 CLBs, with 144 I/O Pins, 175-Pin PGA, Commercial Grade; ComponentAvailability: Not for New Design
footprint PP175 (PGA, 175-Leads, Body 42x42mm, Pitch 2.54mm)
3D model XC3190A-PP175 (175-Pin Plastic Pin Grid Array (PP175))
pins: A2 N/C, A3 N/C, A4 I/O (io), A5 I/O (io), A6 I/O (io), A7 I/O (io), A8 I/O (io), A9 I/O (io), A10 I/O (io), A11 I/O (io), A12 I/O (io), A13 I/O (io), A14 I/O (io), A15 N/C, A16 N/C, B1 I/O (io), B2 ~{PWRDN} (in), B3 I/O (io), B4 I/O (io), B5 I/O (io), B6 I/O (io), B7 I/O (io), B8 I/O (io), B9 I/O (io), B10 I/O (io), B11 I/O (io), B12 I/O (io), B13 I/O (io), B14 M1-~{RDATA} (out), B15 M0-RTRIG (in), B16 I/O (io), C1 A8-I/O (io), C2 A9-I/O (io), C3 GND (power), C4 I/O (io), C5 I/O (io), C6 I/O (io), C7 I/O (io), C8 I/O (io), C9 I/O (io), C10 I/O (io), C11 I/O (io), C12 I/O (io), C13 I/O (io), C14 GND (power), C15 M2-I/O (io), C16 I/O (io), D1 A11-I/O (io), D2 I/O (io), D3 VCC (power), D4 TCLKIN-I/O (io), D5 I/O (io), D6 I/O (io), D7 I/O (io), D8 GND (power), D9 VCC (power), D10 I/O (io), D11 I/O (io), D12 I/O (io), D13 I/O (io), D14 VCC (power), D15 I/O (io), D16 ~{LDC}-I/O (io), E1 A7-I/O (io), E2 I/O (io), E3 A10-I/O (io), E14 HDC-I/O (io), E15 I/O (io), E16 I/O (io), F1 I/O (io), F2 A12-I/O (io), F3 I/O (io), F14 I/O (io), F15 I/O (io), F16 I/O (io), G1 I/O (io), G2 I/O (io), G3 I/O (io), G14 I/O (io), G15 I/O (io), G16 I/O (io), H1 A6-I/O (io), H2 A13-I/O (io), H3 VCC (power), H14 VCC (power), H15 ~{INIT}-I/O (io), H16 I/O (io), J1 I/O (io), J2 I/O (io), J3 GND (power), J14 GND (power), J15 I/O (io), J16 I/O (io), K1 A5-I/O (io), K2 A14-I/O (io), K3 I/O (io), K14 I/O (io), K15 I/O (io), K16 I/O (io), L1 I/O (io), L2 A4-I/O (io), L3 I/O (io), L14 I/O (io), L15 I/O (io), L16 I/O (io), M1 A15-I/O (io), M2 I/O (io), M3 A1-CS2-I/O (io), M14 I/O (io), M15 I/O (io), M16 I/O (io), N1 A3-I/O (io), N2 I/O (io), N3 GND (power), N4 DOUT-I/O (io), N5 I/O (io), N6 I/O (io), N7 I/O (io), N8 GND (power), N9 VCC (power), N10 I/O (io), N11 I/O (io), N12 I/O (io), N13 D7-I/O (io), N14 GND (power), N15 I/O (io), N16 I/O (io), P1 A2-I/O (io), P2 A0-~{WS}-I/O (io), P3 VCC (power), P4 I/O (io), P5 RDY/~{BUSY}-~{BCLK}-I/O (io), P6 I/O (io), P7 I/O (io), P8 D3-I/O (io), P9 I/O (io), P10 I/O (io), P11 I/O (io), P12 D6-I/O (io), P13 I/O (io), P14 VCC (power), P15 XTAL2(IN)-I/O (io), P16 I/O (io), R1 I/O (io), R2 CCLK (io), R3 D0-DIN-I/O (io), R4 I/O (io), R5 D1-I/O (io), R6 I/O (io), R7 D2-I/O (io), R8 ~{CS}1-I/O (io), R9 D4-I/O (io), R10 ~{CS}0-I/O (io), R11 I/O (io), R12 I/O (io), R13 I/O (io), R14 DONE-~{PG} (out), R15 ~{RESET} (in), R16 I/O (io), T1 N/C, T2 N/C, T3 N/C, T4 I/O (io), T5 I/O (io), T6 I/O (io), T7 I/O (io), T8 I/O (io), T9 I/O (io), T10 I/O (io), T11 D5-I/O (io), T12 I/O (io), T13 I/O (io), T14 BCLKIN-XTAL1(OUT)-I/O (io), T15 N/C, T16 N/C

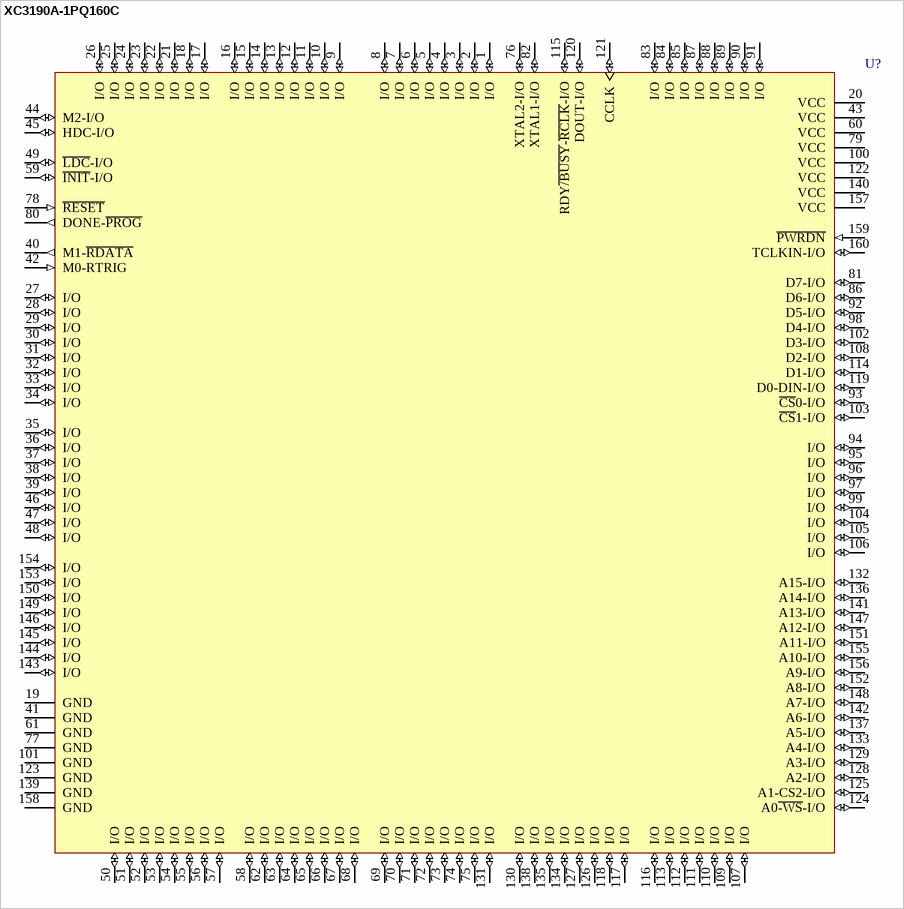
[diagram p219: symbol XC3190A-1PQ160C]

## XC3190A-1PQ160C
designator U?
Logic Cell Array with 320 CLBs, with 138 I/O Pins, 160-Pin PQFP, Commercial Grade; ComponentAvailability: Not for New Design
footprint PQ160_N (QFP, 160-Leads, Body 28 x 28mm, Pitch 0.65mm, IPC Medium Density)
footprint PQ160_L (QFP, 160-Leads, Body 28 x 28mm, Pitch 0.65mm, IPC High Density)
footprint PQ160_M (QFP, 160-Leads, Body 28 x 28mm, Pitch 0.65mm, IPC Low Density)
3D model XC3190A-PQ160 (160-Pin Plastic Quad Flat Pack (PQ160))
pins: 1 I/O (io), 2 I/O (io), 3 I/O (io), 4 I/O (io), 5 I/O (io), 6 I/O (io), 7 I/O (io), 8 I/O (io), 9 I/O (io), 10 I/O (io), 11 I/O (io), 12 I/O (io), 13 I/O (io), 14 I/O (io), 15 I/O (io), 16 I/O (io), 17 I/O (io), 18 I/O (io), 19 GND (power), 20 VCC (power), 21 I/O (io), 22 I/O (io), 23 I/O (io), 24 I/O (io), 25 I/O (io), 26 I/O (io), 27 I/O (io), 28 I/O (io), 29 I/O (io), 30 I/O (io), 31 I/O (io), 32 I/O (io), 33 I/O (io), 34 I/O (io), 35 I/O (io), 36 I/O (io), 37 I/O (io), 38 I/O (io), 39 I/O (io), 40 M1-~{RDATA} (out), 41 GND (power), 42 M0-RTRIG (in), 43 VCC (power), 44 M2-I/O (io), 45 HDC-I/O (io), 46 I/O (io), 47 I/O (io), 48 I/O (io), 49 ~{LDC}-I/O (io), 50 I/O (io), 51 I/O (io), 52 I/O (io), 53 I/O (io), 54 I/O (io), 55 I/O (io), 56 I/O (io), 57 I/O (io), 58 I/O (io), 59 ~{INIT}-I/O (io), 60 VCC (power), 61 GND (power), 62 I/O (io), 63 I/O (io), 64 I/O (io), 65 I/O (io), 66 I/O (io), 67 I/O (io), 68 I/O (io), 69 I/O (io), 70 I/O (io), 71 I/O (io), 72 I/O (io), 73 I/O (io), 74 I/O (io), 75 I/O (io), 76 XTAL2-I/O (io), 77 GND (power), 78 ~{RESET} (in), 79 VCC (power), 80 DONE-~{PROG} (out), 81 D7-I/O (io), 82 XTAL1-I/O (io), 83 I/O (io), 84 I/O (io), 85 I/O (io), 86 D6-I/O (io), 87 I/O (io), 88 I/O (io), 89 I/O (io), 90 I/O (io), 91 I/O (io), 92 D5-I/O (io), 93 ~{CS}0-I/O (io), 94 I/O (io), 95 I/O (io), 96 I/O (io), 97 I/O (io), 98 D4-I/O (io), 99 I/O (io), 100 VCC (power), 101 GND (power), 102 D3-I/O (io), 103 ~{CS}1-I/O (io), 104 I/O (io), 105 I/O (io), 106 I/O (io), 107 I/O (io), 108 D2-I/O (io), 109 I/O (io), 110 I/O (io), 111 I/O (io), 112 I/O (io), 113 I/O (io), 114 D1-I/O (io), 115 RDY~{/BUSY}-~{RCLK}-I/O (io), 116 I/O (io), 117 I/O (io), 118 I/O (io), 119 D0-DIN-I/O (io), 120 DOUT-I/O (io), 121 CCLK (io), 122 VCC (power), 123 GND (power), 124 A0~{-WS}-I/O (io), 125 A1-CS2-I/O (io), 126 I/O (io), 127 I/O (io), 128 A2-I/O (io), 129 A3-I/O (io), 130 I/O (io), 131 I/O (io), 132 A15-I/O (io), 133 A4-I/O (io), 134 I/O (io), 135 I/O (io), 136 A14-I/O (io), 137 A5-I/O (io), 138 I/O (io), 139 GND (power), 140 VCC (power), 141 A13-I/O (io), 142 A6-I/O (io), 143 I/O (io), 144 I/O (io), 145 I/O (io), 146 I/O (io), 147 A12-I/O (io), 148 A7-I/O (io), 149 I/O (io), 150 I/O (io), 151 A11-I/O (io), 152 A8-I/O (io), 153 I/O (io), 154 I/O (io), 155 A10-I/O (io), 156 A9-I/O (io), 157 VCC (power), 158 GND (power), 159 ~{PWRDN} (in), 160 TCLKIN-I/O (io)

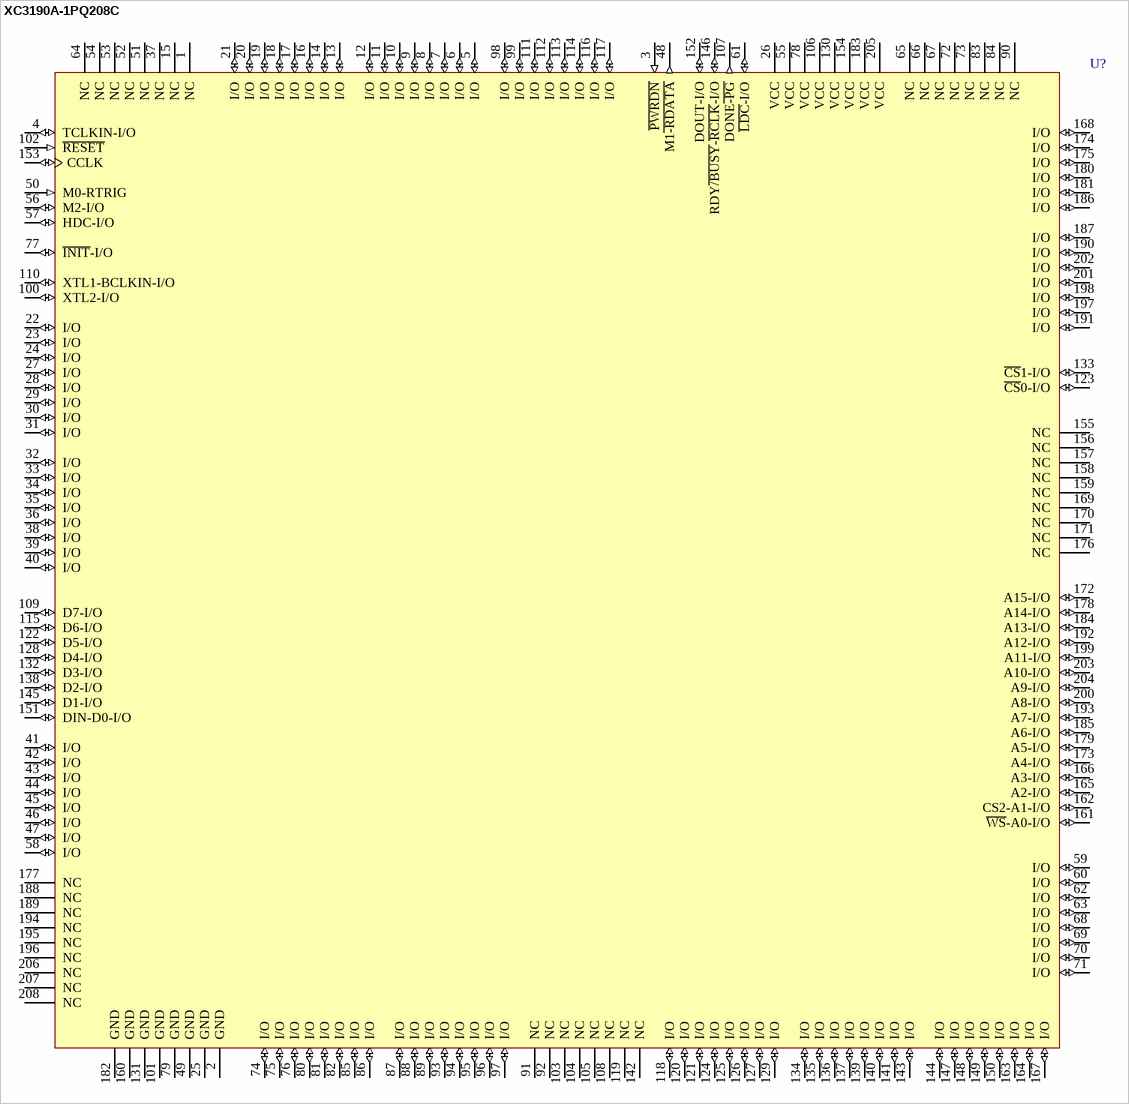
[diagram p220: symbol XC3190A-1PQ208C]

## XC3190A-1PQ208C
designator U?
Logic Cell Array with 320 CLBs, with 144 I/O Pins, 208-Pin PQFP, Commercial Grade; ComponentAvailability: Not for New Design
footprint PQ208_N (Shrink QFP, 208-Leads, Body 28x28mm, Pitch 0.5mm, IPC Medium Density)
footprint PQ208_L (Shrink QFP, 208-Leads, Body 28x28mm, Pitch 0.5mm, IPC High Density)
footprint PQ208_M (Shrink QFP, 208-Leads, Body 28x28mm, Pitch 0.5mm, IPC Low Density)
3D model XC3190A-PQ208 (208-Pin Plastic Quad Flat Pack (PQ208))
pins: 1 NC, 2 GND (power), 3 ~{PWRDN} (in), 4 TCLKIN-I/O (io), 5 I/O (io), 6 I/O (io), 7 I/O (io), 8 I/O (io), 9 I/O (io), 10 I/O (io), 11 I/O (io), 12 I/O (io), 13 I/O (io), 14 I/O (io), 15 NC, 16 I/O (io), 17 I/O (io), 18 I/O (io), 19 I/O (io), 20 I/O (io), 21 I/O (io), 22 I/O (io), 23 I/O (io), 24 I/O (io), 25 GND (power), 26 VCC (power), 27 I/O (io), 28 I/O (io), 29 I/O (io), 30 I/O (io), 31 I/O (io), 32 I/O (io), 33 I/O (io), 34 I/O (io), 35 I/O (io), 36 I/O (io), 37 NC, 38 I/O (io), 39 I/O (io), 40 I/O (io), 41 I/O (io), 42 I/O (io), 43 I/O (io), 44 I/O (io), 45 I/O (io), 46 I/O (io), 47 I/O (io), 48 M1~{-RDATA} (out), 49 GND (power), 50 M0-RTRIG (in), 51 NC, 52 NC, 53 NC, 54 NC, 55 VCC (power), 56 M2-I/O (io), 57 HDC-I/O (io), 58 I/O (io), 59 I/O (io), 60 I/O (io), 61 ~{LDC}-I/O (io), 62 I/O (io), 63 I/O (io), 64 NC, 65 NC, 66 NC, 67 NC, 68 I/O (io), 69 I/O (io), 70 I/O (io), 71 I/O (io), 72 NC, 73 NC, 74 I/O (io), 75 I/O (io), 76 I/O (io), 77 ~{INIT}-I/O (io), 78 VCC (power), 79 GND (power), 80 I/O (io), 81 I/O (io), 82 I/O (io), 83 NC, 84 NC, 85 I/O (io), 86 I/O (io), 87 I/O (io), 88 I/O (io), 89 I/O (io), 90 NC, 91 NC, 92 NC, 93 I/O (io), 94 I/O (io), 95 I/O (io), 96 I/O (io), 97 I/O (io), 98 I/O (io), 99 I/O (io), 100 XTL2-I/O (io), 101 GND (power), 102 ~{RESET} (in), 103 NC, 104 NC, 105 NC, 106 VCC (power), 107 DONE~{-PG} (out), 108 NC, 109 D7-I/O (io), 110 XTL1-BCLKIN-I/O (io), 111 I/O (io), 112 I/O (io), 113 I/O (io), 114 I/O (io), 115 D6-I/O (io), 116 I/O (io), 117 I/O (io), 118 I/O (io), 119 NC, 120 I/O (io), 121 I/O (io), 122 D5-I/O (io), 123 ~{CS}0-I/O (io), 124 I/O (io), 125 I/O (io), 126 I/O (io), 127 I/O (io), 128 D4-I/O (io), 129 I/O (io), 130 VCC (power), 131 GND (power), 132 D3-I/O (io), 133 ~{CS}1-I/O (io), 134 I/O (io), 135 I/O (io), 136 I/O (io), 137 I/O (io), 138 D2-I/O (io), 139 I/O (io), 140 I/O (io), 141 I/O (io), 142 NC, 143 I/O (io), 144 I/O (io), 145 D1-I/O (io), 146 RDY~{/BUSY}-~{RCLK}-I/O (io), 147 I/O (io), 148 I/O (io), 149 I/O (io), 150 I/O (io), 151 DIN-D0-I/O (io), 152 DOUT-I/O (io), 153 CCLK (io), 154 VCC (power), 155 NC, 156 NC, 157 NC, 158 NC, 159 NC, 160 GND (power), 161 ~{WS}-A0-I/O (io), 162 CS2-A1-I/O (io), 163 I/O (io), 164 I/O (io), 165 A2-I/O (io), 166 A3-I/O (io), 167 I/O (io), 168 I/O (io), 169 NC, 170 NC, 171 NC, 172 A15-I/O (io), 173 A4-I/O (io), 174 I/O (io), 175 I/O (io), 176 NC, 177 NC, 178 A14-I/O (io), 179 A5-I/O (io), 180 I/O (io), 181 I/O (io), 182 GND (power), 183 VCC (power), 184 A13-I/O (io), 185 A6-I/O (io), 186 I/O (io), 187 I/O (io), 188 NC, 189 NC, 190 I/O (io), 191 I/O (io), 192 A12-I/O (io), 193 A7-I/O (io), 194 NC, 195 NC, 196 NC, 197 I/O (io), 198 I/O (io), 199 A11-I/O (io), 200 A8-I/O (io), 201 I/O (io), 202 I/O (io), 203 A10-I/O (io), 204 A9-I/O (io), 205 VCC (power), 206 NC, 207 NC, 208 NC

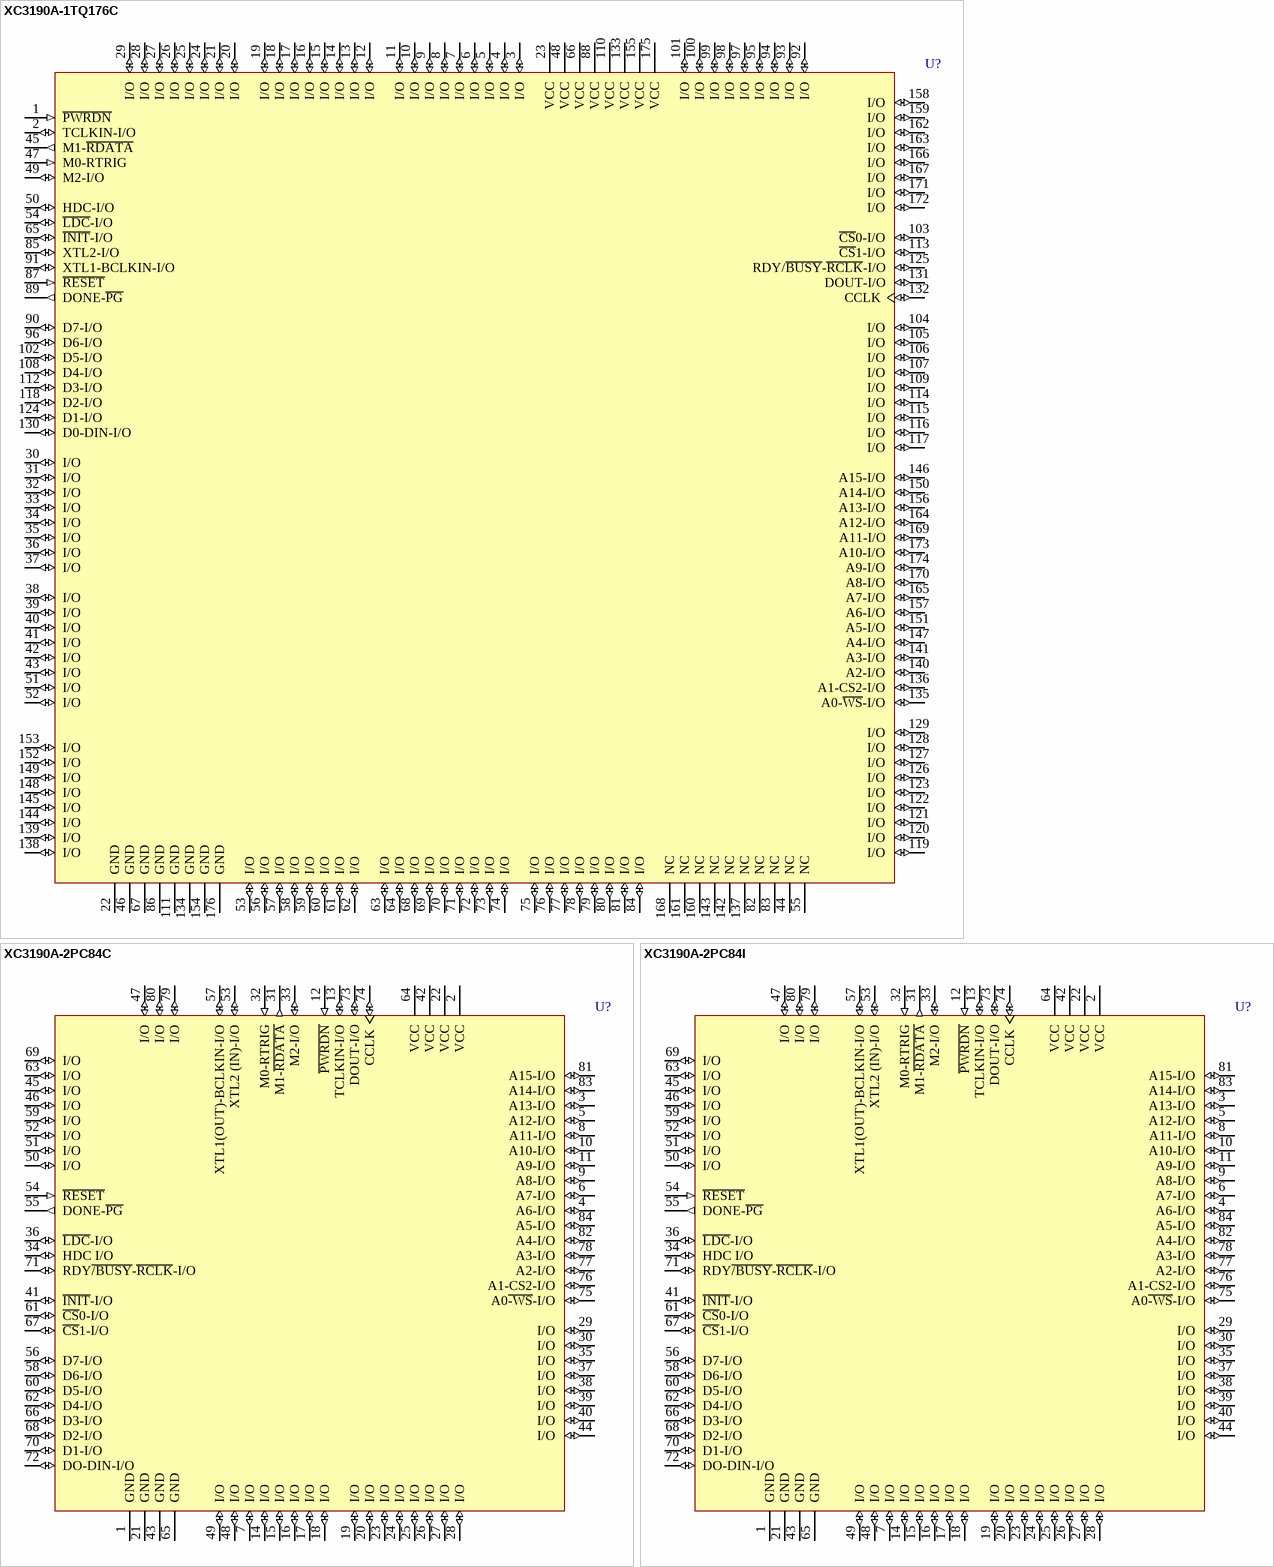
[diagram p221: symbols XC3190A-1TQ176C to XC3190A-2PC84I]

## XC3190A-1TQ176C
designator U?
Logic Cell Array with 320 CLBs, with 144 I/O Pins, 176-Pin TQFP, Commercial Grade; ComponentAvailability: Not for New Design
footprint TQ176_N (Thin QFP, 176-Leads, Body 24x24mm, Pitch 0.5mm, IPC Medium Density)
footprint TQ176_L (Thin QFP, 176-Leads, Body 24x24mm, Pitch 0.5mm, IPC High Density)
footprint TQ176_M (Thin QFP, 176-Leads, Body 24x24mm, Pitch 0.5mm, IPC Low Density)
3D model XC3190A-TQ176 (176-Pin Thin Quad Flat Pack (TQ176))
pins: 1 ~{PWRDN} (in), 2 TCLKIN-I/O (io), 3 I/O (io), 4 I/O (io), 5 I/O (io), 6 I/O (io), 7 I/O (io), 8 I/O (io), 9 I/O (io), 10 I/O (io), 11 I/O (io), 12 I/O (io), 13 I/O (io), 14 I/O (io), 15 I/O (io), 16 I/O (io), 17 I/O (io), 18 I/O (io), 19 I/O (io), 20 I/O (io), 21 I/O (io), 22 GND (power), 23 VCC (power), 24 I/O (io), 25 I/O (io), 26 I/O (io), 27 I/O (io), 28 I/O (io), 29 I/O (io), 30 I/O (io), 31 I/O (io), 32 I/O (io), 33 I/O (io), 34 I/O (io), 35 I/O (io), 36 I/O (io), 37 I/O (io), 38 I/O (io), 39 I/O (io), 40 I/O (io), 41 I/O (io), 42 I/O (io), 43 I/O (io), 44 NC, 45 M1-~{RDATA} (out), 46 GND (power), 47 M0-RTRIG (in), 48 VCC (power), 49 M2-I/O (io), 50 HDC-I/O (io), 51 I/O (io), 52 I/O (io), 53 I/O (io), 54 ~{LDC}-I/O (io), 55 NC, 56 I/O (io), 57 I/O (io), 58 I/O (io), 59 I/O (io), 60 I/O (io), 61 I/O (io), 62 I/O (io), 63 I/O (io), 64 I/O (io), 65 ~{INIT}-I/O (io), 66 VCC (power), 67 GND (power), 68 I/O (io), 69 I/O (io), 70 I/O (io), 71 I/O (io), 72 I/O (io), 73 I/O (io), 74 I/O (io), 75 I/O (io), 76 I/O (io), 77 I/O (io), 78 I/O (io), 79 I/O (io), 80 I/O (io), 81 I/O (io), 82 NC, 83 NC, 84 I/O (io), 85 XTL2-I/O (io), 86 GND (power), 87 ~{RESET} (in), 88 VCC (power), 89 DONE-~{PG} (out), 90 D7-I/O (io), 91 XTL1-BCLKIN-I/O (io), 92 I/O (io), 93 I/O (io), 94 I/O (io), 95 I/O (io), 96 D6-I/O (io), 97 I/O (io), 98 I/O (io), 99 I/O (io), 100 I/O (io), 101 I/O (io), 102 D5-I/O (io), 103 ~{CS}0-I/O (io), 104 I/O (io), 105 I/O (io), 106 I/O (io), 107 I/O (io), 108 D4-I/O (io), 109 I/O (io), 110 VCC (power), 111 GND (power), 112 D3-I/O (io), 113 ~{CS}1-I/O (io), 114 I/O (io), 115 I/O (io), 116 I/O (io), 117 I/O (io), 118 D2-I/O (io), 119 I/O (io), 120 I/O (io), 121 I/O (io), 122 I/O (io), 123 I/O (io), 124 D1-I/O (io), 125 RDY/~{BUSY}-~{RCLK}-I/O (io), 126 I/O (io), 127 I/O (io), 128 I/O (io), 129 I/O (io), 130 D0-DIN-I/O (io), 131 DOUT-I/O (io), 132 CCLK (io), 133 VCC (power), 134 GND (power), 135 A0-~{WS}-I/O (io), 136 A1-CS2-I/O (io), 137 NC, 138 I/O (io), 139 I/O (io), 140 A2-I/O (io), 141 A3-I/O (io), 142 NC, 143 NC, 144 I/O (io), 145 I/O (io), 146 A15-I/O (io), 147 A4-I/O (io), 148 I/O (io), 149 I/O (io), 150 A14-I/O (io), 151 A5-I/O (io), 152 I/O (io), 153 I/O (io), 154 GND (power), 155 VCC (power), 156 A13-I/O (io), 157 A6-I/O (io), 158 I/O (io), 159 I/O (io), 160 NC, 161 NC, 162 I/O (io), 163 I/O (io), 164 A12-I/O (io), 165 A7-I/O (io), 166 I/O (io), 167 I/O (io), 168 NC, 169 A11-I/O (io), 170 A8-I/O (io), 171 I/O (io), 172 I/O (io), 173 A10-I/O (io), 174 A9-I/O (io), 175 VCC (power), 176 GND (power)

## XC3190A-2PC84C
designator U?
Logic Cell Array with 320 CLBs, with 70 I/O Pins, 84-Pin PLCC, Commercial Grade; ComponentAvailability: Not for New Design
footprint PC84_N (Leaded Chip Carrier, 84-Leads, Body 29.3x29.3mm, Pitch 1.27mm, IPC Medium Density)
footprint PC84_L (Leaded Chip Carrier, 84-Leads, Body 29.3x29.3mm, Pitch 1.27mm, IPC High Density)
footprint PC84_M (Leaded Chip Carrier, 84-Leads, Body 29.3x29.3mm, Pitch 1.27mm, IPC Low Density)
3D model XC3190A-PC84 (84-Pin Plastic Leaded Chip Carrier (PC84))
pins: 1 GND (power), 2 VCC (power), 3 A13-I/O (io), 4 A6-I/O (io), 5 A12-I/O (io), 6 A7-I/O (io), 7 I/O (io), 8 A11-I/O (io), 9 A8-I/O (io), 10 A10-I/O (io), 11 A9-I/O (io), 12 ~{PWRDN} (in), 13 TCLKIN-I/O (io), 14 I/O (io), 15 I/O (io), 16 I/O (io), 17 I/O (io), 18 I/O (io), 19 I/O (io), 20 I/O (io), 21 GND (power), 22 VCC (power), 23 I/O (io), 24 I/O (io), 25 I/O (io), 26 I/O (io), 27 I/O (io), 28 I/O (io), 29 I/O (io), 30 I/O (io), 31 M1-~{RDATA} (out), 32 M0-RTRIG (in), 33 M2-I/O (io), 34 HDC I/O (io), 35 I/O (io), 36 ~{LDC}-I/O (io), 37 I/O (io), 38 I/O (io), 39 I/O (io), 40 I/O (io), 41 ~{INIT}-I/O (io), 42 VCC (power), 43 GND (power), 44 I/O (io), 45 I/O (io), 46 I/O (io), 47 I/O (io), 48 I/O (io), 49 I/O (io), 50 I/O (io), 51 I/O (io), 52 I/O (io), 53 XTL2 (IN)-I/O (io), 54 ~{RESET} (in), 55 DONE-~{PG} (out), 56 D7-I/O (io), 57 XTL1(OUT)-BCLKIN-I/O (io), 58 D6-I/O (io), 59 I/O (io), 60 D5-I/O (io), 61 ~{CS}0-I/O (io), 62 D4-I/O (io), 63 I/O (io), 64 VCC (power), 65 GND (power), 66 D3-I/O (io), 67 ~{CS}1-I/O (io), 68 D2-I/O (io), 69 I/O (io), 70 D1-I/O (io), 71 RDY~{/BUSY}-~{RCLK}-I/O (io), 72 DO-DIN-I/O (io), 73 DOUT-I/O (io), 74 CCLK (io), 75 A0~{-WS}-I/O (io), 76 A1-CS2-I/O (io), 77 A2-I/O (io), 78 A3-I/O (io), 79 I/O (io), 80 I/O (io), 81 A15-I/O (io), 82 A4-I/O (io), 83 A14-I/O (io), 84 A5-I/O (io)

## XC3190A-2PC84I
designator U?
Logic Cell Array with 320 CLBs, with 70 I/O Pins, 84-Pin PLCC, Industrial Grade; ComponentAvailability: Not for New Design
footprint PC84_N (Leaded Chip Carrier, 84-Leads, Body 29.3x29.3mm, Pitch 1.27mm, IPC Medium Density)
footprint PC84_L (Leaded Chip Carrier, 84-Leads, Body 29.3x29.3mm, Pitch 1.27mm, IPC High Density)
footprint PC84_M (Leaded Chip Carrier, 84-Leads, Body 29.3x29.3mm, Pitch 1.27mm, IPC Low Density)
3D model XC3190A-PC84 (84-Pin Plastic Leaded Chip Carrier (PC84))
pins: 1 GND (power), 2 VCC (power), 3 A13-I/O (io), 4 A6-I/O (io), 5 A12-I/O (io), 6 A7-I/O (io), 7 I/O (io), 8 A11-I/O (io), 9 A8-I/O (io), 10 A10-I/O (io), 11 A9-I/O (io), 12 ~{PWRDN} (in), 13 TCLKIN-I/O (io), 14 I/O (io), 15 I/O (io), 16 I/O (io), 17 I/O (io), 18 I/O (io), 19 I/O (io), 20 I/O (io), 21 GND (power), 22 VCC (power), 23 I/O (io), 24 I/O (io), 25 I/O (io), 26 I/O (io), 27 I/O (io), 28 I/O (io), 29 I/O (io), 30 I/O (io), 31 M1-~{RDATA} (out), 32 M0-RTRIG (in), 33 M2-I/O (io), 34 HDC I/O (io), 35 I/O (io), 36 ~{LDC}-I/O (io), 37 I/O (io), 38 I/O (io), 39 I/O (io), 40 I/O (io), 41 ~{INIT}-I/O (io), 42 VCC (power), 43 GND (power), 44 I/O (io), 45 I/O (io), 46 I/O (io), 47 I/O (io), 48 I/O (io), 49 I/O (io), 50 I/O (io), 51 I/O (io), 52 I/O (io), 53 XTL2 (IN)-I/O (io), 54 ~{RESET} (in), 55 DONE-~{PG} (out), 56 D7-I/O (io), 57 XTL1(OUT)-BCLKIN-I/O (io), 58 D6-I/O (io), 59 I/O (io), 60 D5-I/O (io), 61 ~{CS}0-I/O (io), 62 D4-I/O (io), 63 I/O (io), 64 VCC (power), 65 GND (power), 66 D3-I/O (io), 67 ~{CS}1-I/O (io), 68 D2-I/O (io), 69 I/O (io), 70 D1-I/O (io), 71 RDY~{/BUSY}-~{RCLK}-I/O (io), 72 DO-DIN-I/O (io), 73 DOUT-I/O (io), 74 CCLK (io), 75 A0~{-WS}-I/O (io), 76 A1-CS2-I/O (io), 77 A2-I/O (io), 78 A3-I/O (io), 79 I/O (io), 80 I/O (io), 81 A15-I/O (io), 82 A4-I/O (io), 83 A14-I/O (io), 84 A5-I/O (io)

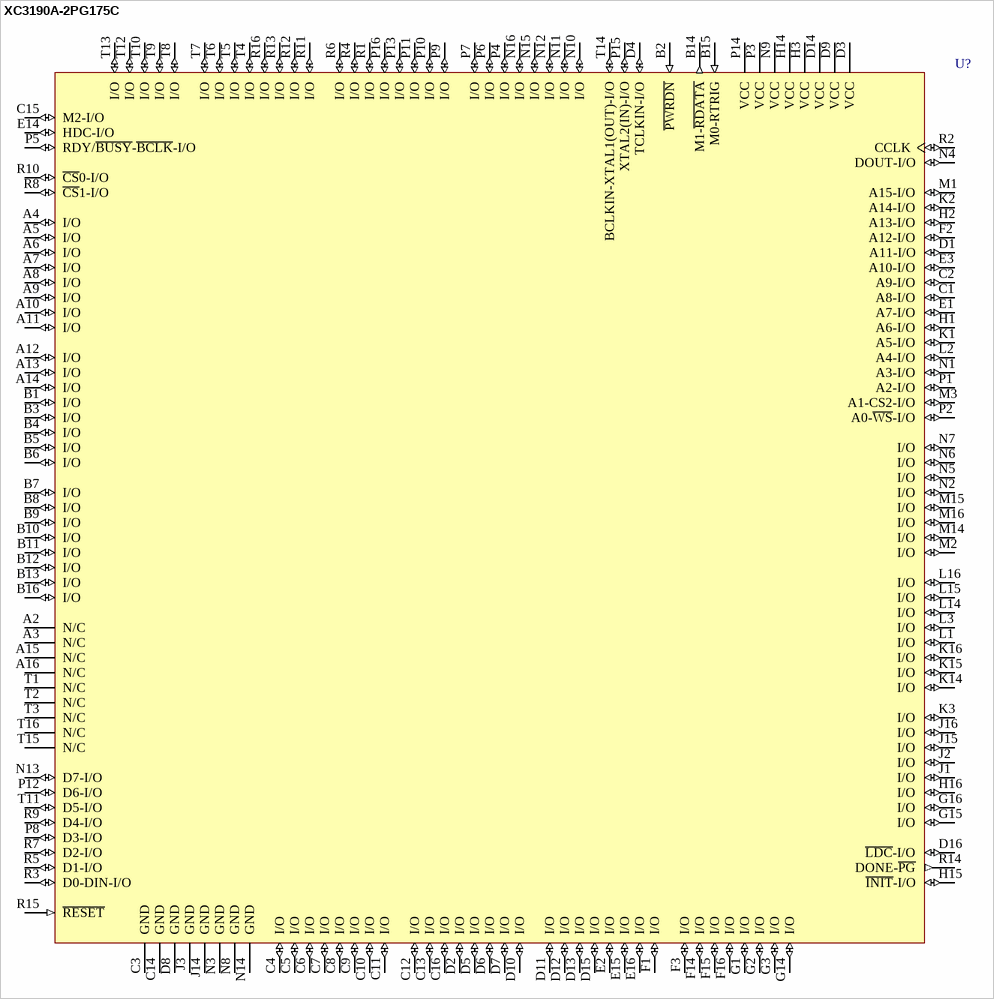
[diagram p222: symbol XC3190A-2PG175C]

## XC3190A-2PG175C
designator U?
Logic Cell Array with 320 CLBs, with 144 I/O Pins, 175-Pin PGA, Commercial Grade; ComponentAvailability: Not for New Design
footprint PG175 (PGA, 175-Leads, Body 42x42mm, Pitch 2.54mm)
3D model XC3190A-PG175 (175-Pin Ceramic Pin Grid Array (PG175))
pins: A2 N/C, A3 N/C, A4 I/O (io), A5 I/O (io), A6 I/O (io), A7 I/O (io), A8 I/O (io), A9 I/O (io), A10 I/O (io), A11 I/O (io), A12 I/O (io), A13 I/O (io), A14 I/O (io), A15 N/C, A16 N/C, B1 I/O (io), B2 ~{PWRDN} (in), B3 I/O (io), B4 I/O (io), B5 I/O (io), B6 I/O (io), B7 I/O (io), B8 I/O (io), B9 I/O (io), B10 I/O (io), B11 I/O (io), B12 I/O (io), B13 I/O (io), B14 M1-~{RDATA} (out), B15 M0-RTRIG (in), B16 I/O (io), C1 A8-I/O (io), C2 A9-I/O (io), C3 GND (power), C4 I/O (io), C5 I/O (io), C6 I/O (io), C7 I/O (io), C8 I/O (io), C9 I/O (io), C10 I/O (io), C11 I/O (io), C12 I/O (io), C13 I/O (io), C14 GND (power), C15 M2-I/O (io), C16 I/O (io), D1 A11-I/O (io), D2 I/O (io), D3 VCC (power), D4 TCLKIN-I/O (io), D5 I/O (io), D6 I/O (io), D7 I/O (io), D8 GND (power), D9 VCC (power), D10 I/O (io), D11 I/O (io), D12 I/O (io), D13 I/O (io), D14 VCC (power), D15 I/O (io), D16 ~{LDC}-I/O (io), E1 A7-I/O (io), E2 I/O (io), E3 A10-I/O (io), E14 HDC-I/O (io), E15 I/O (io), E16 I/O (io), F1 I/O (io), F2 A12-I/O (io), F3 I/O (io), F14 I/O (io), F15 I/O (io), F16 I/O (io), G1 I/O (io), G2 I/O (io), G3 I/O (io), G14 I/O (io), G15 I/O (io), G16 I/O (io), H1 A6-I/O (io), H2 A13-I/O (io), H3 VCC (power), H14 VCC (power), H15 ~{INIT}-I/O (io), H16 I/O (io), J1 I/O (io), J2 I/O (io), J3 GND (power), J14 GND (power), J15 I/O (io), J16 I/O (io), K1 A5-I/O (io), K2 A14-I/O (io), K3 I/O (io), K14 I/O (io), K15 I/O (io), K16 I/O (io), L1 I/O (io), L2 A4-I/O (io), L3 I/O (io), L14 I/O (io), L15 I/O (io), L16 I/O (io), M1 A15-I/O (io), M2 I/O (io), M3 A1-CS2-I/O (io), M14 I/O (io), M15 I/O (io), M16 I/O (io), N1 A3-I/O (io), N2 I/O (io), N3 GND (power), N4 DOUT-I/O (io), N5 I/O (io), N6 I/O (io), N7 I/O (io), N8 GND (power), N9 VCC (power), N10 I/O (io), N11 I/O (io), N12 I/O (io), N13 D7-I/O (io), N14 GND (power), N15 I/O (io), N16 I/O (io), P1 A2-I/O (io), P2 A0-~{WS}-I/O (io), P3 VCC (power), P4 I/O (io), P5 RDY/~{BUSY}-~{BCLK}-I/O (io), P6 I/O (io), P7 I/O (io), P8 D3-I/O (io), P9 I/O (io), P10 I/O (io), P11 I/O (io), P12 D6-I/O (io), P13 I/O (io), P14 VCC (power), P15 XTAL2(IN)-I/O (io), P16 I/O (io), R1 I/O (io), R2 CCLK (io), R3 D0-DIN-I/O (io), R4 I/O (io), R5 D1-I/O (io), R6 I/O (io), R7 D2-I/O (io), R8 ~{CS}1-I/O (io), R9 D4-I/O (io), R10 ~{CS}0-I/O (io), R11 I/O (io), R12 I/O (io), R13 I/O (io), R14 DONE-~{PG} (out), R15 ~{RESET} (in), R16 I/O (io), T1 N/C, T2 N/C, T3 N/C, T4 I/O (io), T5 I/O (io), T6 I/O (io), T7 I/O (io), T8 I/O (io), T9 I/O (io), T10 I/O (io), T11 D5-I/O (io), T12 I/O (io), T13 I/O (io), T14 BCLKIN-XTAL1(OUT)-I/O (io), T15 N/C, T16 N/C

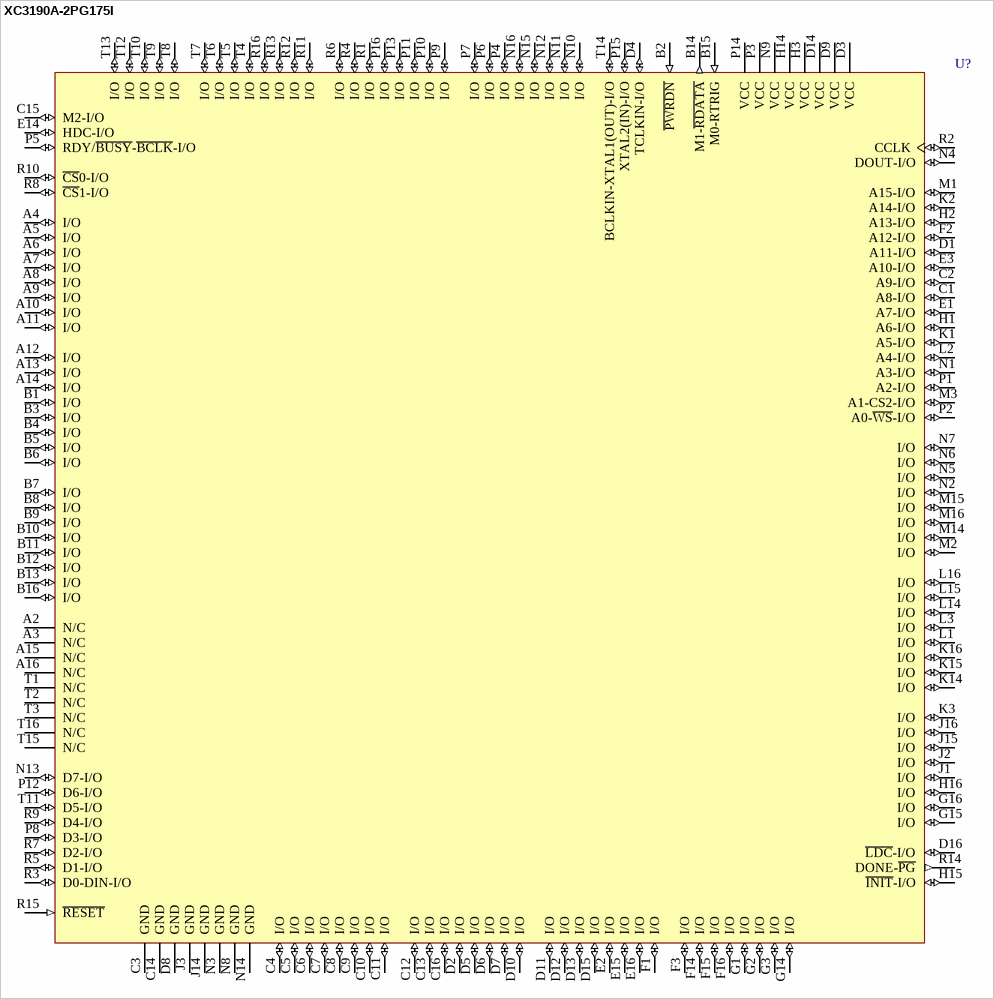
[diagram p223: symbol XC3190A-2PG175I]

## XC3190A-2PG175I
designator U?
Logic Cell Array with 320 CLBs, with 144 I/O Pins, 175-Pin PGA, Industrial Grade; ComponentAvailability: Not for New Design
footprint PG175 (PGA, 175-Leads, Body 42x42mm, Pitch 2.54mm)
3D model XC3190A-PG175 (175-Pin Ceramic Pin Grid Array (PG175))
pins: A2 N/C, A3 N/C, A4 I/O (io), A5 I/O (io), A6 I/O (io), A7 I/O (io), A8 I/O (io), A9 I/O (io), A10 I/O (io), A11 I/O (io), A12 I/O (io), A13 I/O (io), A14 I/O (io), A15 N/C, A16 N/C, B1 I/O (io), B2 ~{PWRDN} (in), B3 I/O (io), B4 I/O (io), B5 I/O (io), B6 I/O (io), B7 I/O (io), B8 I/O (io), B9 I/O (io), B10 I/O (io), B11 I/O (io), B12 I/O (io), B13 I/O (io), B14 M1-~{RDATA} (out), B15 M0-RTRIG (in), B16 I/O (io), C1 A8-I/O (io), C2 A9-I/O (io), C3 GND (power), C4 I/O (io), C5 I/O (io), C6 I/O (io), C7 I/O (io), C8 I/O (io), C9 I/O (io), C10 I/O (io), C11 I/O (io), C12 I/O (io), C13 I/O (io), C14 GND (power), C15 M2-I/O (io), C16 I/O (io), D1 A11-I/O (io), D2 I/O (io), D3 VCC (power), D4 TCLKIN-I/O (io), D5 I/O (io), D6 I/O (io), D7 I/O (io), D8 GND (power), D9 VCC (power), D10 I/O (io), D11 I/O (io), D12 I/O (io), D13 I/O (io), D14 VCC (power), D15 I/O (io), D16 ~{LDC}-I/O (io), E1 A7-I/O (io), E2 I/O (io), E3 A10-I/O (io), E14 HDC-I/O (io), E15 I/O (io), E16 I/O (io), F1 I/O (io), F2 A12-I/O (io), F3 I/O (io), F14 I/O (io), F15 I/O (io), F16 I/O (io), G1 I/O (io), G2 I/O (io), G3 I/O (io), G14 I/O (io), G15 I/O (io), G16 I/O (io), H1 A6-I/O (io), H2 A13-I/O (io), H3 VCC (power), H14 VCC (power), H15 ~{INIT}-I/O (io), H16 I/O (io), J1 I/O (io), J2 I/O (io), J3 GND (power), J14 GND (power), J15 I/O (io), J16 I/O (io), K1 A5-I/O (io), K2 A14-I/O (io), K3 I/O (io), K14 I/O (io), K15 I/O (io), K16 I/O (io), L1 I/O (io), L2 A4-I/O (io), L3 I/O (io), L14 I/O (io), L15 I/O (io), L16 I/O (io), M1 A15-I/O (io), M2 I/O (io), M3 A1-CS2-I/O (io), M14 I/O (io), M15 I/O (io), M16 I/O (io), N1 A3-I/O (io), N2 I/O (io), N3 GND (power), N4 DOUT-I/O (io), N5 I/O (io), N6 I/O (io), N7 I/O (io), N8 GND (power), N9 VCC (power), N10 I/O (io), N11 I/O (io), N12 I/O (io), N13 D7-I/O (io), N14 GND (power), N15 I/O (io), N16 I/O (io), P1 A2-I/O (io), P2 A0-~{WS}-I/O (io), P3 VCC (power), P4 I/O (io), P5 RDY/~{BUSY}-~{BCLK}-I/O (io), P6 I/O (io), P7 I/O (io), P8 D3-I/O (io), P9 I/O (io), P10 I/O (io), P11 I/O (io), P12 D6-I/O (io), P13 I/O (io), P14 VCC (power), P15 XTAL2(IN)-I/O (io), P16 I/O (io), R1 I/O (io), R2 CCLK (io), R3 D0-DIN-I/O (io), R4 I/O (io), R5 D1-I/O (io), R6 I/O (io), R7 D2-I/O (io), R8 ~{CS}1-I/O (io), R9 D4-I/O (io), R10 ~{CS}0-I/O (io), R11 I/O (io), R12 I/O (io), R13 I/O (io), R14 DONE-~{PG} (out), R15 ~{RESET} (in), R16 I/O (io), T1 N/C, T2 N/C, T3 N/C, T4 I/O (io), T5 I/O (io), T6 I/O (io), T7 I/O (io), T8 I/O (io), T9 I/O (io), T10 I/O (io), T11 D5-I/O (io), T12 I/O (io), T13 I/O (io), T14 BCLKIN-XTAL1(OUT)-I/O (io), T15 N/C, T16 N/C

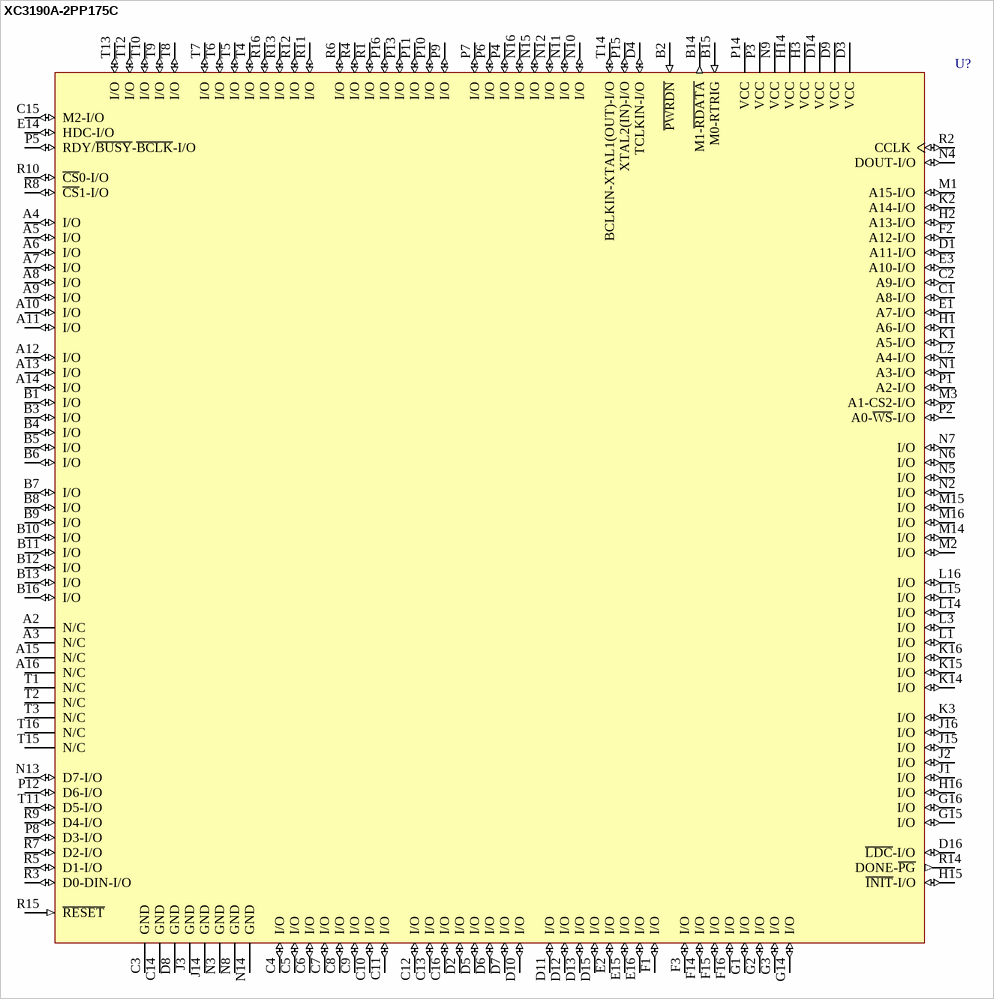
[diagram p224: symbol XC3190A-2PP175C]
